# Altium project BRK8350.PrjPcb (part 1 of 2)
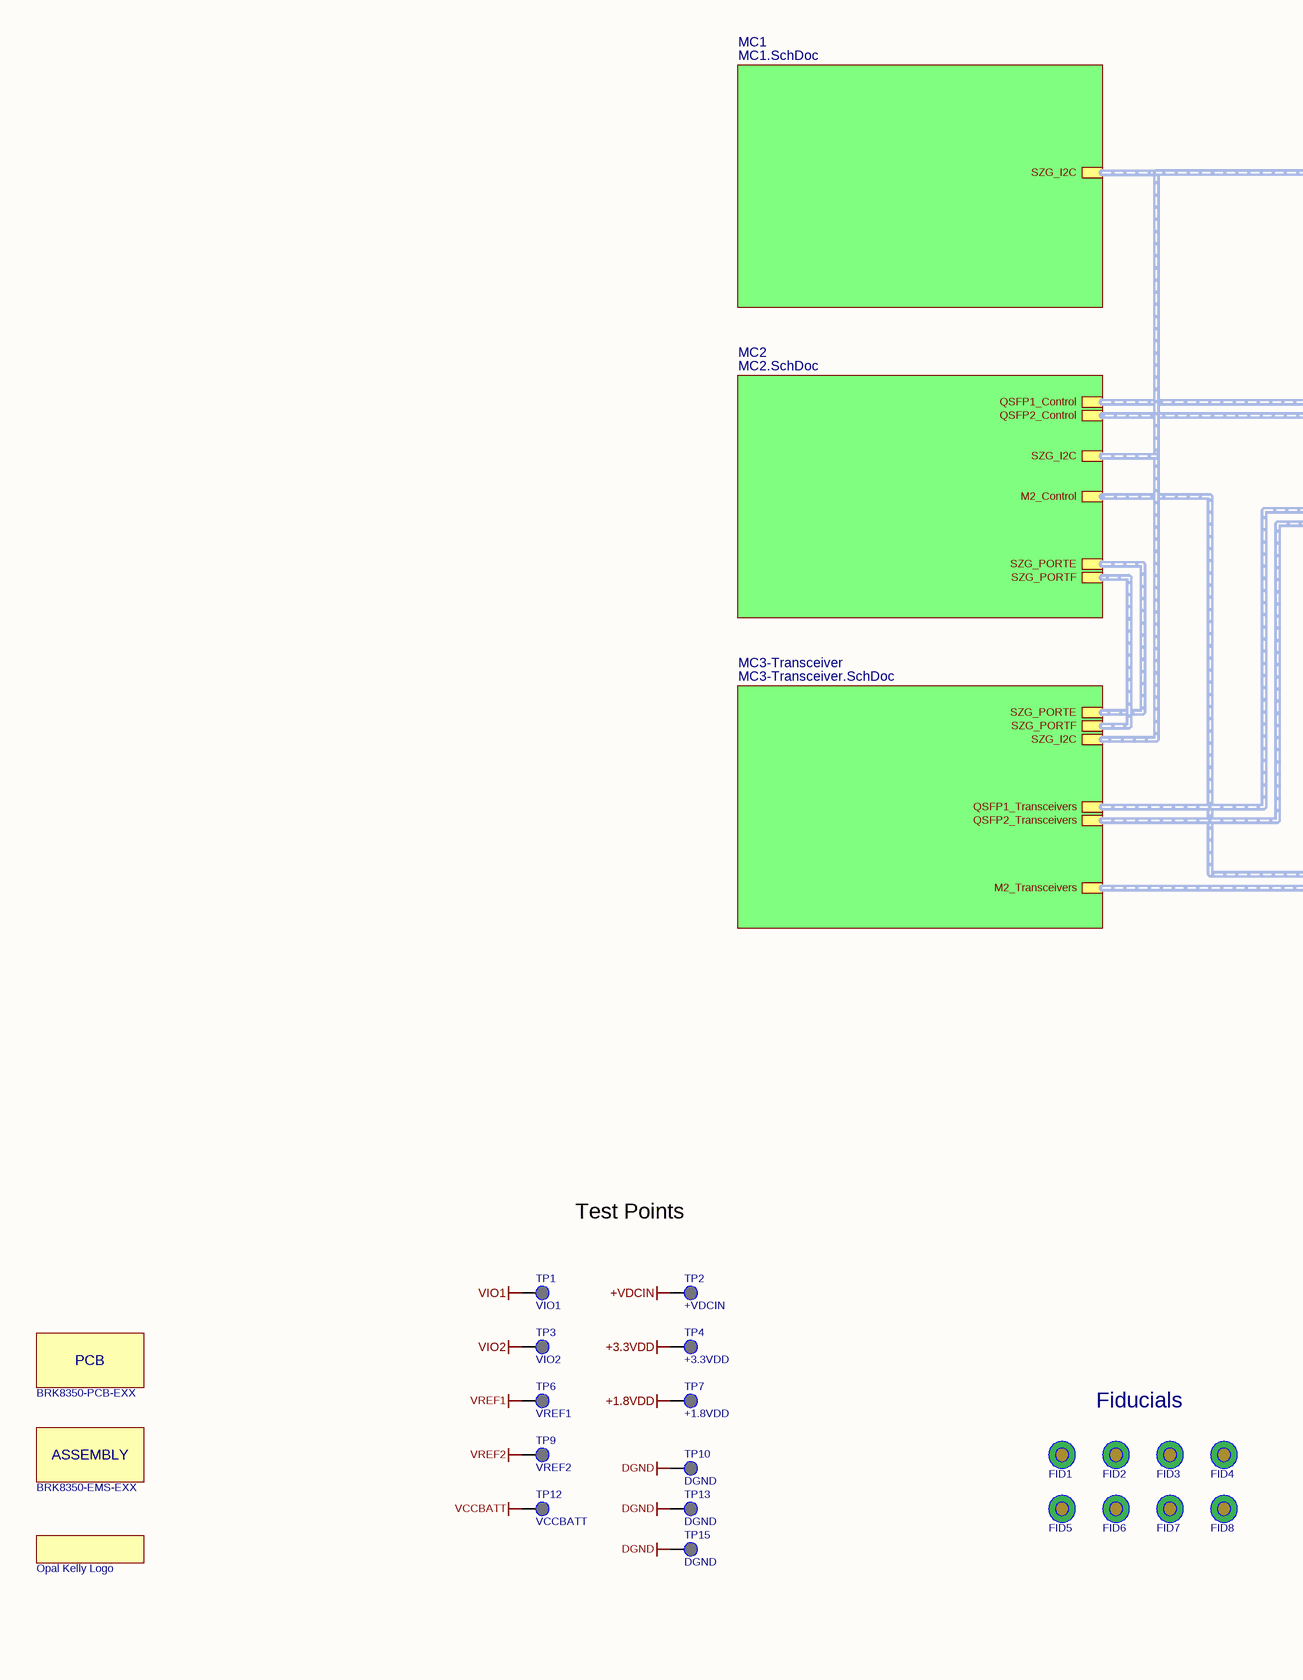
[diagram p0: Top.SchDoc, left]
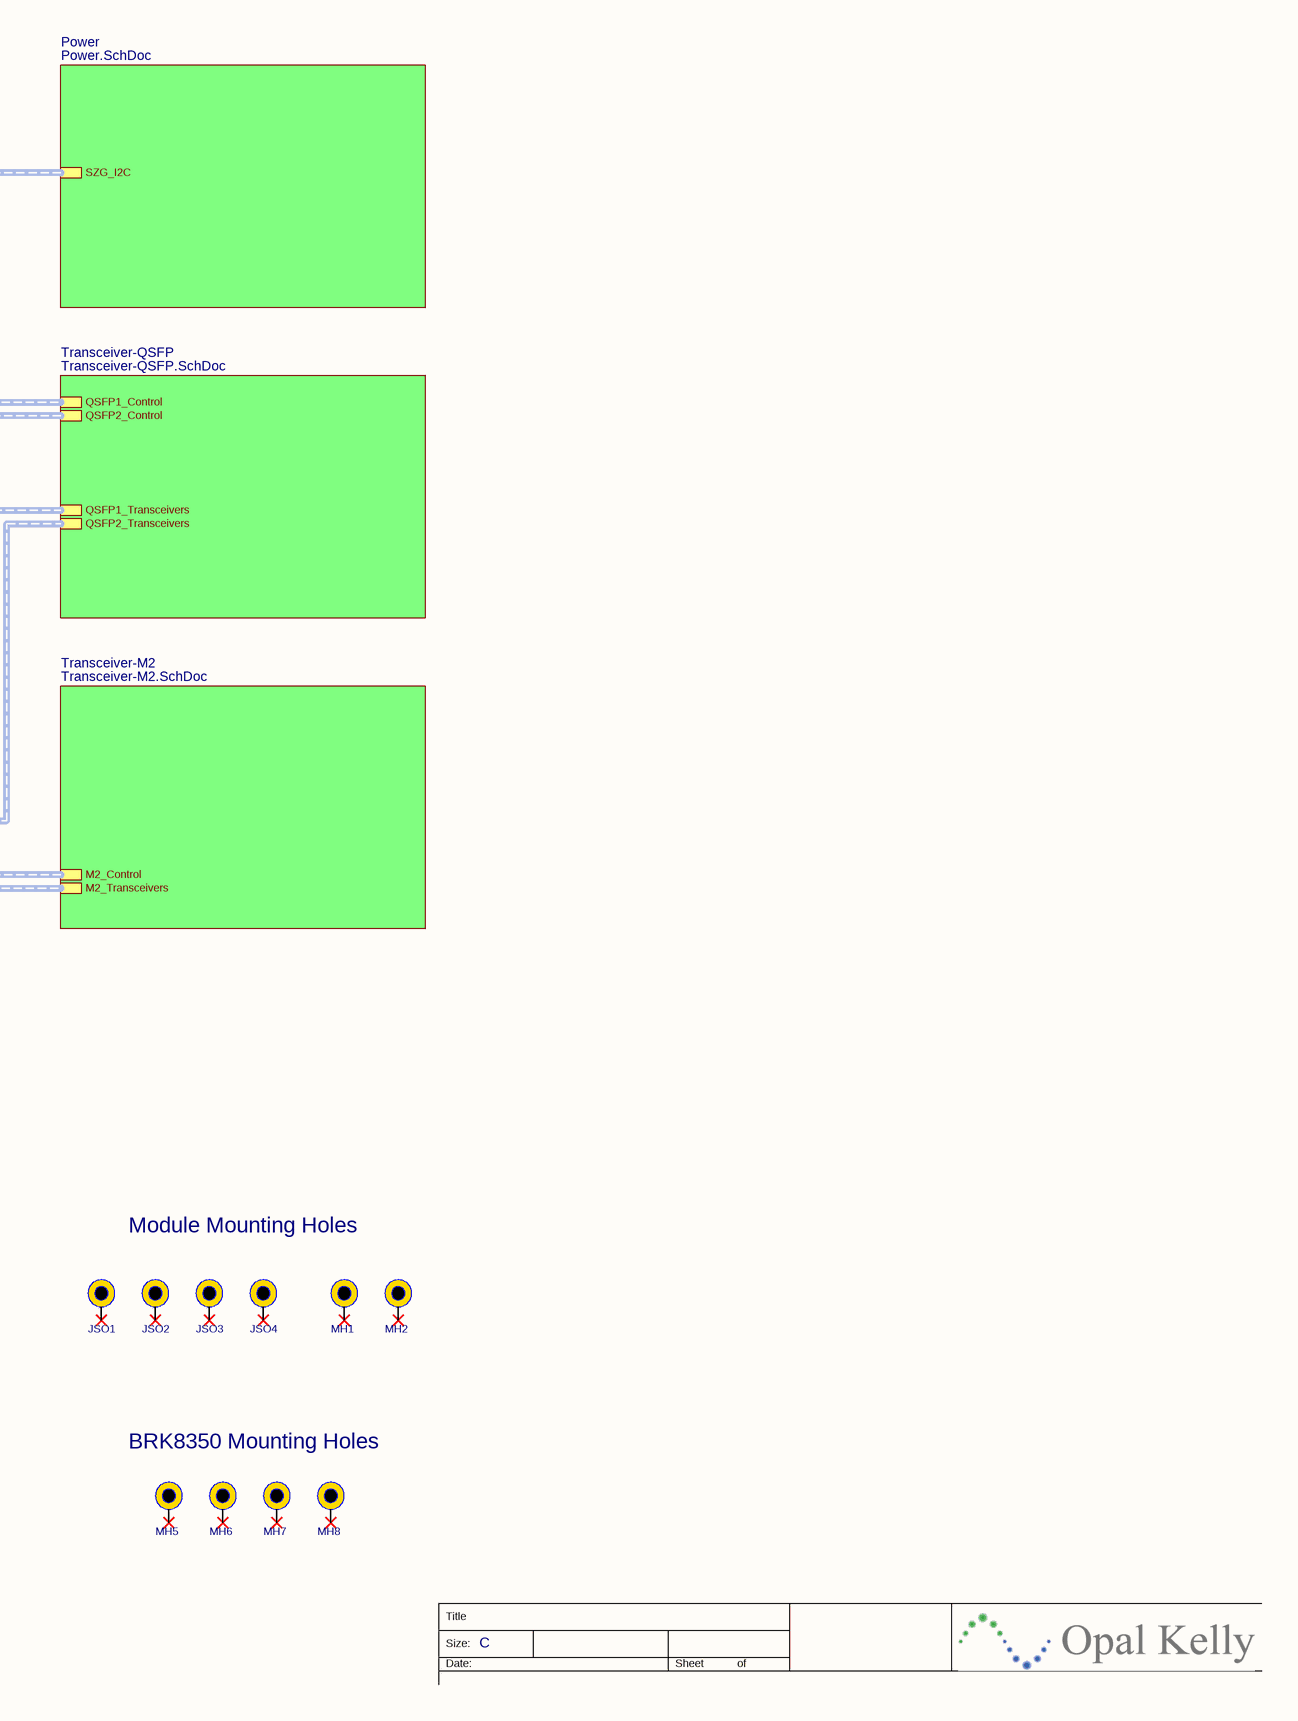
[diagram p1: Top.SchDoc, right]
BOM_Revision: 02; Part_Number: BRK8350; PCB_Revision: E; VariantBoms: Default=001770
7 sheets, 281 parts. Net scope: hierarchical (ports join the sheet entries above them; power ports are global).
Board file: BRK8350.PcbDoc
Sheets:
  Top.SchDoc
    Transceiver-QSFP = Transceiver-QSFP.SchDoc
    MC2 = MC2.SchDoc
    MC1 = MC1.SchDoc
    Power = Power.SchDoc
    Transceiver-M2 = Transceiver-M2.SchDoc
    MC3-Transceiver = MC3-Transceiver.SchDoc

## Sheet Top.SchDoc: BRK8350 - Top Level
size C; Organization: Opal Kelly; Address1: 13500 SW 72nd Ave STE 100; Address3: Portland, OR  97223; Address4: http://www.opalkelly.com; DocumentNumber: xxx; Revision: 1; SheetNumber: 1; SheetTotal: 7; PageSetup: Record=PageOptions¦CenterHorizontal=True¦CenterVertical=True¦PrintScale=0.52¦XCorrection=1.00¦YCorrection=1.00¦PrintKind=0¦BorderSize=5000000¦LeftOffset=0¦BottomOffset=0¦Orientation=2¦PaperLength=1000¦PaperWidth=1000¦Scale=100¦PaperSource=15¦PrintQuality=600¦MediaType=1¦DitherType=10¦PaperKind=Letter¦PrintScaleMode=1

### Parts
*1  Opal Kelly Logo  [okLogo-23x5]
ASSY1  BRK8350-EMS-EXX  (mechanical)
FID1  FIDUCIAL  [FID1MM/2MM-SS]  (value not drawn)
FID2  FIDUCIAL  [FID1MM/2MM-SS]  (value not drawn)
FID3  FIDUCIAL  [FID1MM/2MM-SS]  (value not drawn)
FID4  FIDUCIAL  [FID1MM/2MM-SS]  (value not drawn)
FID5  FIDUCIAL  [FID1MM/2MM-SS]  (value not drawn)
FID6  FIDUCIAL  [FID1MM/2MM-SS]  (value not drawn)
FID7  FIDUCIAL  [FID1MM/2MM-SS]  (value not drawn)
FID8  FIDUCIAL  [FID1MM/2MM-SS]  (value not drawn)
JSO1  Jack Screw Standoff  [JSO-0515-01]  (value not drawn)
JSO2  Jack Screw Standoff  [JSO-0515-01]  (value not drawn)
JSO3  Jack Screw Standoff  [JSO-0515-01]  (value not drawn)
JSO4  Jack Screw Standoff  [JSO-0515-01]  (value not drawn)
MH1  MTG  [MTG-3.2/6.5-PTH]  (value not drawn)
MH2  MTG  [MTG-3.2/6.5-PTH]  (value not drawn)
MH5  MTG  [MTG-3.2/6.5-PTH]  (value not drawn)
MH6  MTG  [MTG-3.2/6.5-PTH]  (value not drawn)
MH7  MTG  [MTG-3.2/6.5-PTH]  (value not drawn)
MH8  MTG  [MTG-3.2/6.5-PTH]  (value not drawn)
PCB1  BRK8350-PCB-EXX  (mechanical)
TP1  VIO1  [TP-PTH-65/100]
TP2  +VDCIN  [TP-PTH-65/100]
TP3  VIO2  [TP-PTH-65/100]
TP4  +3.3VDD  [TP-PTH-65/100]
TP6  VREF1  [TP-PTH-65/100]
TP7  +1.8VDD  [TP-PTH-65/100]
TP9  VREF2  [TP-PTH-65/100]
TP10  DGND  [TP-PTH-65/100]
TP12  VCCBATT  [TP-PTH-65/100]
TP13  DGND  [TP-PTH-65/100]
TP15  DGND  [TP-PTH-65/100]

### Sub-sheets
MC1 = MC1.SchDoc: SZG_I2C (harness I2C)
MC2 = MC2.SchDoc: SZG_PORTE (harness SYZYGY_TXR4), SZG_PORTF (harness SYZYGY_TXR4), QSFP1_Control (harness QSFP_Control), M2_Control (harness M2_Control), QSFP2_Control (harness QSFP_Control), SZG_I2C (harness I2C)
MC3-Transceiver = MC3-Transceiver.SchDoc: SZG_PORTE (harness SYZYGY_TXR4), SZG_PORTF (harness SYZYGY_TXR4), SZG_I2C (harness I2C), M2_Transceivers (harness M2_Transceivers), QSFP1_Transceivers (harness QSFP_Transceivers), QSFP2_Transceivers (harness QSFP_Transceivers)
Power = Power.SchDoc: SZG_I2C (harness I2C)
Transceiver-M2 = Transceiver-M2.SchDoc: M2_Transceivers (harness M2_Transceivers), M2_Control (harness M2_Control)
Transceiver-QSFP = Transceiver-QSFP.SchDoc: QSFP1_Control (harness QSFP_Control), QSFP2_Control (harness QSFP_Control), QSFP1_Transceivers (harness QSFP_Transceivers), QSFP2_Transceivers (harness QSFP_Transceivers)

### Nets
+1.8VDD: TP7.1(PIN)
+3.3VDD: TP4.1(PIN)
+VDCIN: TP2.1(PIN)
DGND: TP10.1(PIN) TP13.1(PIN) TP15.1(PIN)
VCCBATT: TP12.1(PIN)
VIO1: TP1.1(PIN)
VIO2: TP3.1(PIN)
VREF1: TP6.1(PIN)
VREF2: TP9.1(PIN)

Not connected (* = marked no-connect by the designer): JSO1 1*; JSO2 1*; JSO3 1*; JSO4 1*; MH1 1*; MH2 1*; MH5 1*; MH6 1*; MH7 1*; MH8 1*

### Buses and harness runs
harness sheet MC1/SZG_I2C = sheet MC2/SZG_I2C = sheet MC3-Transceiver/SZG_I2C = sheet Power/SZG_I2C
harness sheet MC2/M2_Control = sheet Transceiver-M2/M2_Control
harness sheet MC2/QSFP1_Control = sheet Transceiver-QSFP/QSFP1_Control
harness sheet MC2/QSFP2_Control = sheet Transceiver-QSFP/QSFP2_Control
harness sheet MC2/SZG_PORTE = sheet MC3-Transceiver/SZG_PORTE
harness sheet MC2/SZG_PORTF = sheet MC3-Transceiver/SZG_PORTF
harness sheet MC3-Transceiver/M2_Transceivers = sheet Transceiver-M2/M2_Transceivers
harness sheet MC3-Transceiver/QSFP1_Transceivers = sheet Transceiver-QSFP/QSFP1_Transceivers
harness sheet MC3-Transceiver/QSFP2_Transceivers = sheet Transceiver-QSFP/QSFP2_Transceivers

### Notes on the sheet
- Test Points
- Module Mounting Holes
- Fiducials
- BRK8350 Mounting Holes
- Title
- Size:
- Date:
- C
- Sheet
- of

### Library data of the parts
*1 = OKLOGO: partnumber: ALIGNI_IGNORE
ASSY1 = 001928: Assembly Service; Partnumber: 001928; manufacturer: PCB Assembly Cost; description: BRK8350 PCB assembly
FID1-FID8 = FIDUCIAL: PCB fiducial; partnumber: ALIGNI_IGNORE
JSO1-JSO4 = 001879: Mounting hole; Partnumber: 001879; manufacturer: Samtec
MH1 MH2 MH5-MH8 = MTG: Mounting hole; partnumber: ALIGNI_IGNORE
PCB1 = 001929: PCB; Partnumber: 001929; manufacturer: Generic PCB Manufacturer; description: PCB for BRK8350
TP1-TP4 TP6 TP7 TP9 TP10 TP12 TP13 TP15 = TP-PTH-65/100: Test point, plated through-hole, 65/100mil; partnumber: ALIGNI_IGNORE

## Sheet Transceiver-QSFP.SchDoc: BRK8350 - QSFP
size C; Author: Casey Smith; Organization: Opal Kelly; Address1: 13500 SW 72nd Ave STE 100; Address2: Portland, OR 97223; Address3: 217.391.3724; Address4: http://www.opalkelly.com; DocumentNumber: xxx; Revision: 1; SheetNumber: 5; SheetTotal: 7
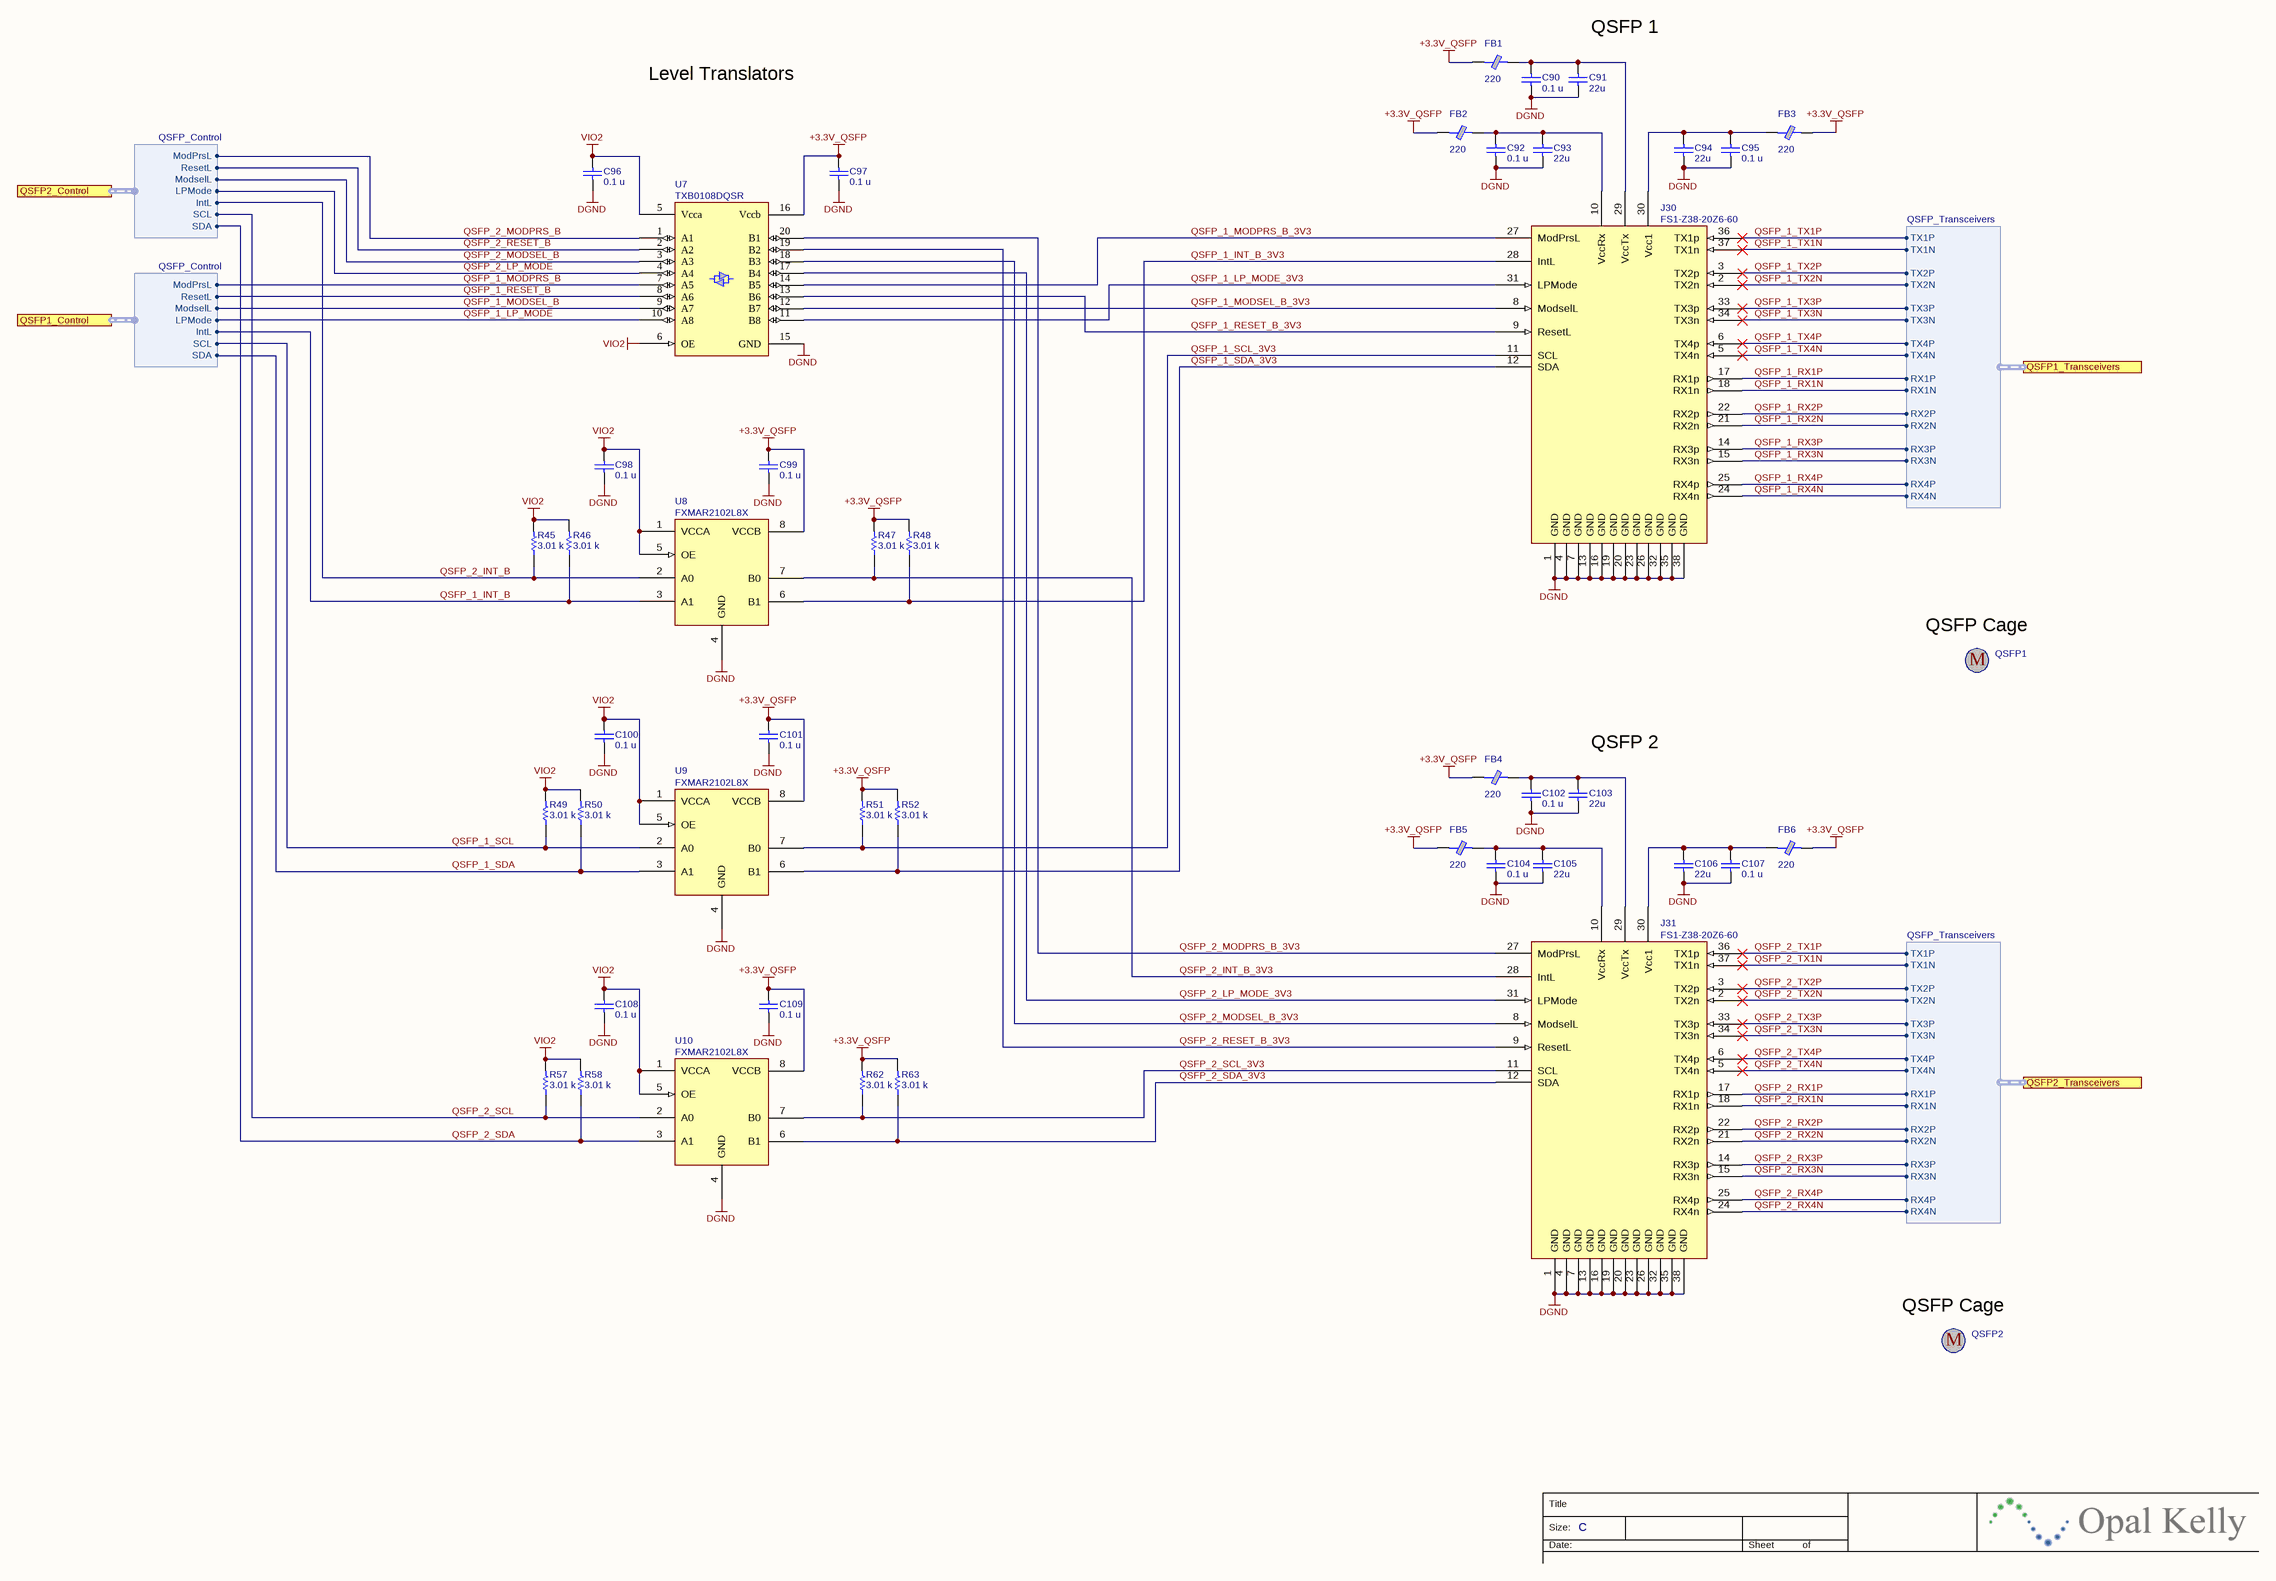
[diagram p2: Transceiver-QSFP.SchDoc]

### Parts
C90  value 0.1 u  [CAPC1005X06A]  (hidden comment: SM-0402, 10%, 10v)
C91  value 22u  [CAPC3216N]  (hidden comment: SM-1206, 10%, 10v, X7R)
C92  value 0.1 u  [CAPC1005X06A]  (hidden comment: SM-0402, 10%, 10v)
C93  value 22u  [CAPC3216N]  (hidden comment: SM-1206, 10%, 10v, X7R)
C94  value 22u  [CAPC3216N]  (hidden comment: SM-1206, 10%, 10v, X7R)
C95  value 0.1 u  [CAPC1005X06A]  (hidden comment: SM-0402, 10%, 10v)
C96  value 0.1 u  [CAPC1005X06A]  (hidden comment: SM-0402, 10%, 10v)
C97  value 0.1 u  [CAPC1005X06A]  (hidden comment: SM-0402, 10%, 10v)
C98  value 0.1 u  [CAPC1005X06A]  (hidden comment: SM-0402, 10%, 10v)
C99  value 0.1 u  [CAPC1005X06A]  (hidden comment: SM-0402, 10%, 10v)
C100  value 0.1 u  [CAPC1005X06A]  (hidden comment: SM-0402, 10%, 10v)
C101  value 0.1 u  [CAPC1005X06A]  (hidden comment: SM-0402, 10%, 10v)
C102  value 0.1 u  [CAPC1005X06A]  (hidden comment: SM-0402, 10%, 10v)
C103  value 22u  [CAPC3216N]  (hidden comment: SM-1206, 10%, 10v, X7R)
C104  value 0.1 u  [CAPC1005X06A]  (hidden comment: SM-0402, 10%, 10v)
C105  value 22u  [CAPC3216N]  (hidden comment: SM-1206, 10%, 10v, X7R)
C106  value 22u  [CAPC3216N]  (hidden comment: SM-1206, 10%, 10v, X7R)
C107  value 0.1 u  [CAPC1005X06A]  (hidden comment: SM-0402, 10%, 10v)
C108  value 0.1 u  [CAPC1005X06A]  (hidden comment: SM-0402, 10%, 10v)
C109  value 0.1 u  [CAPC1005X06A]  (hidden comment: SM-0402, 10%, 10v)
FB1  value 220  [RESC2012N]  (hidden comment: 220 OHM 2000MA 0805)
FB2  value 220  [RESC2012N]  (hidden comment: 220 OHM 2000MA 0805)
FB3  value 220  [RESC2012N]  (hidden comment: 220 OHM 2000MA 0805)
FB4  value 220  [RESC2012N]  (hidden comment: 220 OHM 2000MA 0805)
FB5  value 220  [RESC2012N]  (hidden comment: 220 OHM 2000MA 0805)
FB6  value 220  [RESC2012N]  (hidden comment: 220 OHM 2000MA 0805)
J30  FS1-Z38-20Z6-60  [QSFP28_RECEPTACLE_SFF-8679]
J31  FS1-Z38-20Z6-60  [QSFP28_RECEPTACLE_SFF-8679]
QSFP1  Pressfit  [QSFP28_SINGLE_CAGE]  (value not drawn)
QSFP2  Pressfit  [QSFP28_SINGLE_CAGE]  (value not drawn)
R45  value 3.01 k  [RESC1005X06A]  (hidden comment: SM-0402, 1%, 1/16W)
R46  value 3.01 k  [RESC1005X06A]  (hidden comment: SM-0402, 1%, 1/16W)
R47  value 3.01 k  [RESC1005X06A]  (hidden comment: SM-0402, 1%, 1/16W)
R48  value 3.01 k  [RESC1005X06A]  (hidden comment: SM-0402, 1%, 1/16W)
R49  value 3.01 k  [RESC1005X06A]  (hidden comment: SM-0402, 1%, 1/16W)
R50  value 3.01 k  [RESC1005X06A]  (hidden comment: SM-0402, 1%, 1/16W)
R51  value 3.01 k  [RESC1005X06A]  (hidden comment: SM-0402, 1%, 1/16W)
R52  value 3.01 k  [RESC1005X06A]  (hidden comment: SM-0402, 1%, 1/16W)
R57  value 3.01 k  [RESC1005X06A]  (hidden comment: SM-0402, 1%, 1/16W)
R58  value 3.01 k  [RESC1005X06A]  (hidden comment: SM-0402, 1%, 1/16W)
R62  value 3.01 k  [RESC1005X06A]  (hidden comment: SM-0402, 1%, 1/16W)
R63  value 3.01 k  [RESC1005X06A]  (hidden comment: SM-0402, 1%, 1/16W)
U7  TXB0108DQSR  [TXB0108DQSR]
U8  FXMAR2102L8X  [FXMAR2102L8X]
U9  FXMAR2102L8X  [FXMAR2102L8X]
U10  FXMAR2102L8X  [FXMAR2102L8X]

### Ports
QSFP1_Control (harness QSFP_Control), QSFP1_Transceivers (harness QSFP_Transceivers), QSFP2_Control (harness QSFP_Control), QSFP2_Transceivers (harness QSFP_Transceivers)

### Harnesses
QSFP_Transceivers: TX1P, TX1N, TX2P, TX2N, TX3P, TX3N, TX4P, TX4N, RX1P, RX1N, RX2P, RX2N, RX3P, RX3N, RX4P, RX4N
QSFP_Control: ModPrsL, IntL, LPMode, ModselL, ResetL, SCL, SDA

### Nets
+3.3V_QSFP: C97.2 C99.2 C101.2 C109.2 FB1.1 FB2.1 FB3.2 FB4.1 FB5.1 FB6.2 R47.2 R48.2 R51.2 R52.2 R62.2 R63.2 U7.16(Vccb) U8.8(VCCB) U9.8(VCCB) U10.8(VCCB)
DGND: C90.1 C91.1 C92.1 C93.1 C94.1 C95.1 C96.1 C97.1 C98.1 C99.1 C100.1 C101.1 C102.1 C103.1 C104.1 C105.1 C106.1 C107.1 C108.1 C109.1 J30.1(GND) J30.4(GND) J30.7(GND) J30.13(GND) J30.16(GND) J30.19(GND) J30.20(GND) J30.23(GND) J30.26(GND) J30.32(GND) J30.35(GND) J30.38(GND) J31.1(GND) J31.4(GND) J31.7(GND) J31.13(GND) J31.16(GND) J31.19(GND) J31.20(GND) J31.23(GND) J31.26(GND) J31.32(GND) J31.35(GND) J31.38(GND) U7.15(GND) U8.4(GND) U9.4(GND) U10.4(GND)
VIO2: C96.2 C98.2 C100.2 C108.2 R45.2 R46.2 R49.2 R50.2 R57.2 R58.2 U7.5(Vcca) U7.6(OE) U8.1(VCCA) U8.5(OE) U9.1(VCCA) U9.5(OE) U10.1(VCCA) U10.5(OE)
QSFP_1_INT_B: R46.1 U8.3(A1) ; port QSFP1_Control.IntL
QSFP_1_INT_B_3V3: J30.28(IntL) R48.1 U8.6(B1)
QSFP_1_LP_MODE: U7.10(A8) ; port QSFP1_Control.LPMode
QSFP_1_LP_MODE_3V3: J30.31(LPMode) U7.11(B8)
QSFP_1_MODPRS_B: U7.7(A5) ; port QSFP1_Control.ModPrsL
QSFP_1_MODPRS_B_3V3: J30.27(ModPrsL) U7.14(B5)
QSFP_1_MODSEL_B: U7.9(A7) ; port QSFP1_Control.ModselL
QSFP_1_MODSEL_B_3V3: J30.8(ModselL) U7.12(B7)
QSFP_1_RESET_B: U7.8(A6) ; port QSFP1_Control.ResetL
QSFP_1_RESET_B_3V3: J30.9(ResetL) U7.13(B6)
QSFP_1_RX1N: J30.18(RX1n) ; port QSFP1_Transceivers.RX1N
QSFP_1_RX1P: J30.17(RX1p) ; port QSFP1_Transceivers.RX1P
QSFP_1_RX2N: J30.21(RX2n) ; port QSFP1_Transceivers.RX2N
QSFP_1_RX2P: J30.22(RX2p) ; port QSFP1_Transceivers.RX2P
QSFP_1_RX3N: J30.15(RX3n) ; port QSFP1_Transceivers.RX3N
QSFP_1_RX3P: J30.14(RX3p) ; port QSFP1_Transceivers.RX3P
QSFP_1_RX4N: J30.24(RX4n) ; port QSFP1_Transceivers.RX4N
QSFP_1_RX4P: J30.25(RX4p) ; port QSFP1_Transceivers.RX4P
QSFP_1_SCL: R49.1 U9.2(A0) ; port QSFP1_Control.SCL
QSFP_1_SCL_3V3: J30.11(SCL) R51.1 U9.7(B0)
QSFP_1_SDA: R50.1 U9.3(A1) ; port QSFP1_Control.SDA
QSFP_1_SDA_3V3: J30.12(SDA) R52.1 U9.6(B1)
QSFP_1_TX1N: J30.37(TX1n) ; port QSFP1_Transceivers.TX1N
QSFP_1_TX1P: J30.36(TX1p) ; port QSFP1_Transceivers.TX1P
QSFP_1_TX2N: J30.2(TX2n) ; port QSFP1_Transceivers.TX2N
QSFP_1_TX2P: J30.3(TX2p) ; port QSFP1_Transceivers.TX2P
QSFP_1_TX3N: J30.34(TX3n) ; port QSFP1_Transceivers.TX3N
QSFP_1_TX3P: J30.33(TX3p) ; port QSFP1_Transceivers.TX3P
QSFP_1_TX4N: J30.5(TX4n) ; port QSFP1_Transceivers.TX4N
QSFP_1_TX4P: J30.6(TX4p) ; port QSFP1_Transceivers.TX4P
QSFP_2_INT_B: R45.1 U8.2(A0) ; port QSFP2_Control.IntL
QSFP_2_INT_B_3V3: J31.28(IntL) R47.1 U8.7(B0)
QSFP_2_LP_MODE: U7.4(A4) ; port QSFP2_Control.LPMode
QSFP_2_LP_MODE_3V3: J31.31(LPMode) U7.17(B4)
QSFP_2_MODPRS_B: U7.1(A1) ; port QSFP2_Control.ModPrsL
QSFP_2_MODPRS_B_3V3: J31.27(ModPrsL) U7.20(B1)
QSFP_2_MODSEL_B: U7.3(A3) ; port QSFP2_Control.ModselL
QSFP_2_MODSEL_B_3V3: J31.8(ModselL) U7.18(B3)
QSFP_2_RESET_B: U7.2(A2) ; port QSFP2_Control.ResetL
QSFP_2_RESET_B_3V3: J31.9(ResetL) U7.19(B2)
QSFP_2_RX1N: J31.18(RX1n) ; port QSFP2_Transceivers.RX1N
QSFP_2_RX1P: J31.17(RX1p) ; port QSFP2_Transceivers.RX1P
QSFP_2_RX2N: J31.21(RX2n) ; port QSFP2_Transceivers.RX2N
QSFP_2_RX2P: J31.22(RX2p) ; port QSFP2_Transceivers.RX2P
QSFP_2_RX3N: J31.15(RX3n) ; port QSFP2_Transceivers.RX3N
QSFP_2_RX3P: J31.14(RX3p) ; port QSFP2_Transceivers.RX3P
QSFP_2_RX4N: J31.24(RX4n) ; port QSFP2_Transceivers.RX4N
QSFP_2_RX4P: J31.25(RX4p) ; port QSFP2_Transceivers.RX4P
QSFP_2_SCL: R57.1 U10.2(A0) ; port QSFP2_Control.SCL
QSFP_2_SCL_3V3: J31.11(SCL) R62.1 U10.7(B0)
QSFP_2_SDA: R58.1 U10.3(A1) ; port QSFP2_Control.SDA
QSFP_2_SDA_3V3: J31.12(SDA) R63.1 U10.6(B1)
QSFP_2_TX1N: J31.37(TX1n) ; port QSFP2_Transceivers.TX1N
QSFP_2_TX1P: J31.36(TX1p) ; port QSFP2_Transceivers.TX1P
QSFP_2_TX2N: J31.2(TX2n) ; port QSFP2_Transceivers.TX2N
QSFP_2_TX2P: J31.3(TX2p) ; port QSFP2_Transceivers.TX2P
QSFP_2_TX3N: J31.34(TX3n) ; port QSFP2_Transceivers.TX3N
QSFP_2_TX3P: J31.33(TX3p) ; port QSFP2_Transceivers.TX3P
QSFP_2_TX4N: J31.5(TX4n) ; port QSFP2_Transceivers.TX4N
QSFP_2_TX4P: J31.6(TX4p) ; port QSFP2_Transceivers.TX4P
NetC90_2: C90.2 C91.2 FB1.2 J30.29(VccTx)
NetC92_2: C92.2 C93.2 FB2.2 J30.10(VccRx)
NetC94_2: C94.2 C95.2 FB3.1 J30.30(Vcc1)
NetC102_2: C102.2 C103.2 FB4.2 J31.29(VccTx)
NetC104_2: C104.2 C105.2 FB5.2 J31.10(VccRx)
NetC106_2: C106.2 C107.2 FB6.1 J31.30(Vcc1)

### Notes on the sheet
- (near C91) QSFP 1
- Level Translators
- (near QSFP1) QSFP Cage
- (near C103) QSFP 2
- (near QSFP2) QSFP Cage
- Title
- Size:
- Date:
- C
- Sheet
- of

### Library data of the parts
C90 C92 C95-C102 C104 C107-C109 = 000070: Partnumber: 000070; manufacturer: Kemet; manufacturer_pn: C0402C104K8PACTU; ValueFloat: 1E-7; id: 750; inventory_price: 0.0023; reorder_quantity: 70000; x_tolerance: 10
C91 C93 C94 C103 C105 C106 = 001284: Partnumber: 001284; manufacturer: Taiyo Yuden; manufacturer_pn: LMK316AB7226KL-TR; ValueFloat: 2.2E-5; id: 60625; inventory_price: 0.14; reorder_quantity: 4000; x_tolerance: 10
FB1-FB6 = 000783: Partnumber: 000783; manufacturer: Murata; manufacturer_pn: BLM21PG221SN1D; id: 12845; inventory_price: 0.02; reorder_quantity: 200
J30 J31 = 001782: Partnumber: 001782; manufacturer: Amphenol; id: 254667; inventory_price: 4
QSFP1 QSFP2 = 001781: Partnumber: 001781; manufacturer: Amphenol; manufacturer_pn: U95-T111-1001; id: 254666; inventory_price: 3.5
R45-R52 R57 R58 R62 R63 = 001126: Partnumber: 001126; manufacturer: Vishay; manufacturer_pn: CRCW04023K01FKED; ValueFloat: 3010; id: 35682; inventory_price: 0.015; x_tolerance: 1
U7 = 001324: Partnumber: 001324; manufacturer: Texas Instruments; id: 94563; inventory_price: 1.67
U8-U10 = 001559: Partnumber: 001559; manufacturer: ON Semiconductor; id: 168047; inventory_price: 0.3

## Sheet MC2.SchDoc: BRK8350 - Mezzanine Connector MC2
size C; Author: Casey Smith; Organization: Opal Kelly; Address1: 13500 SW 72nd Ave STE 100; Address2: Portland, OR 97223; Address3: 217.391.3724; Address4: http://www.opalkelly.com; DocumentNumber: xxx; Revision: 1; SheetNumber: 3; SheetTotal: 7
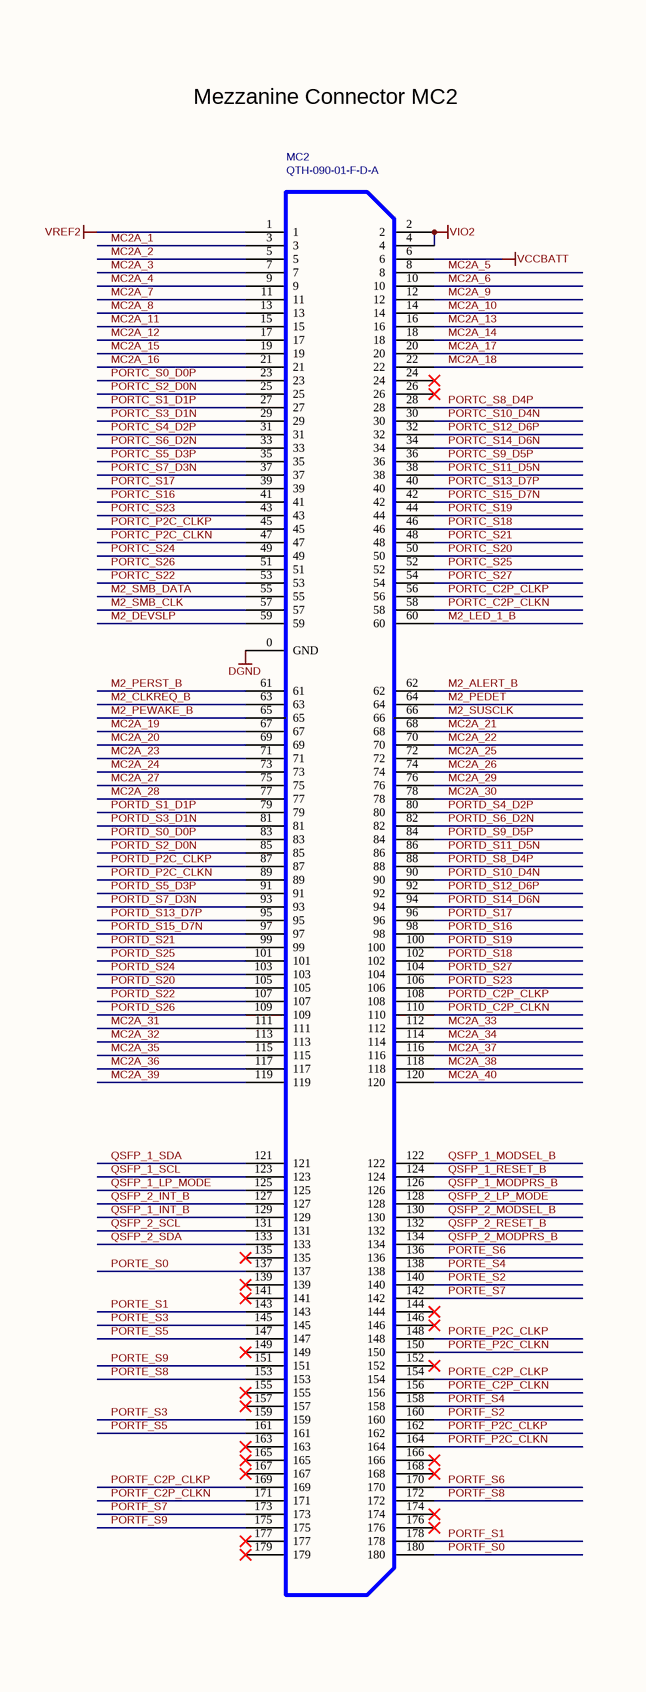
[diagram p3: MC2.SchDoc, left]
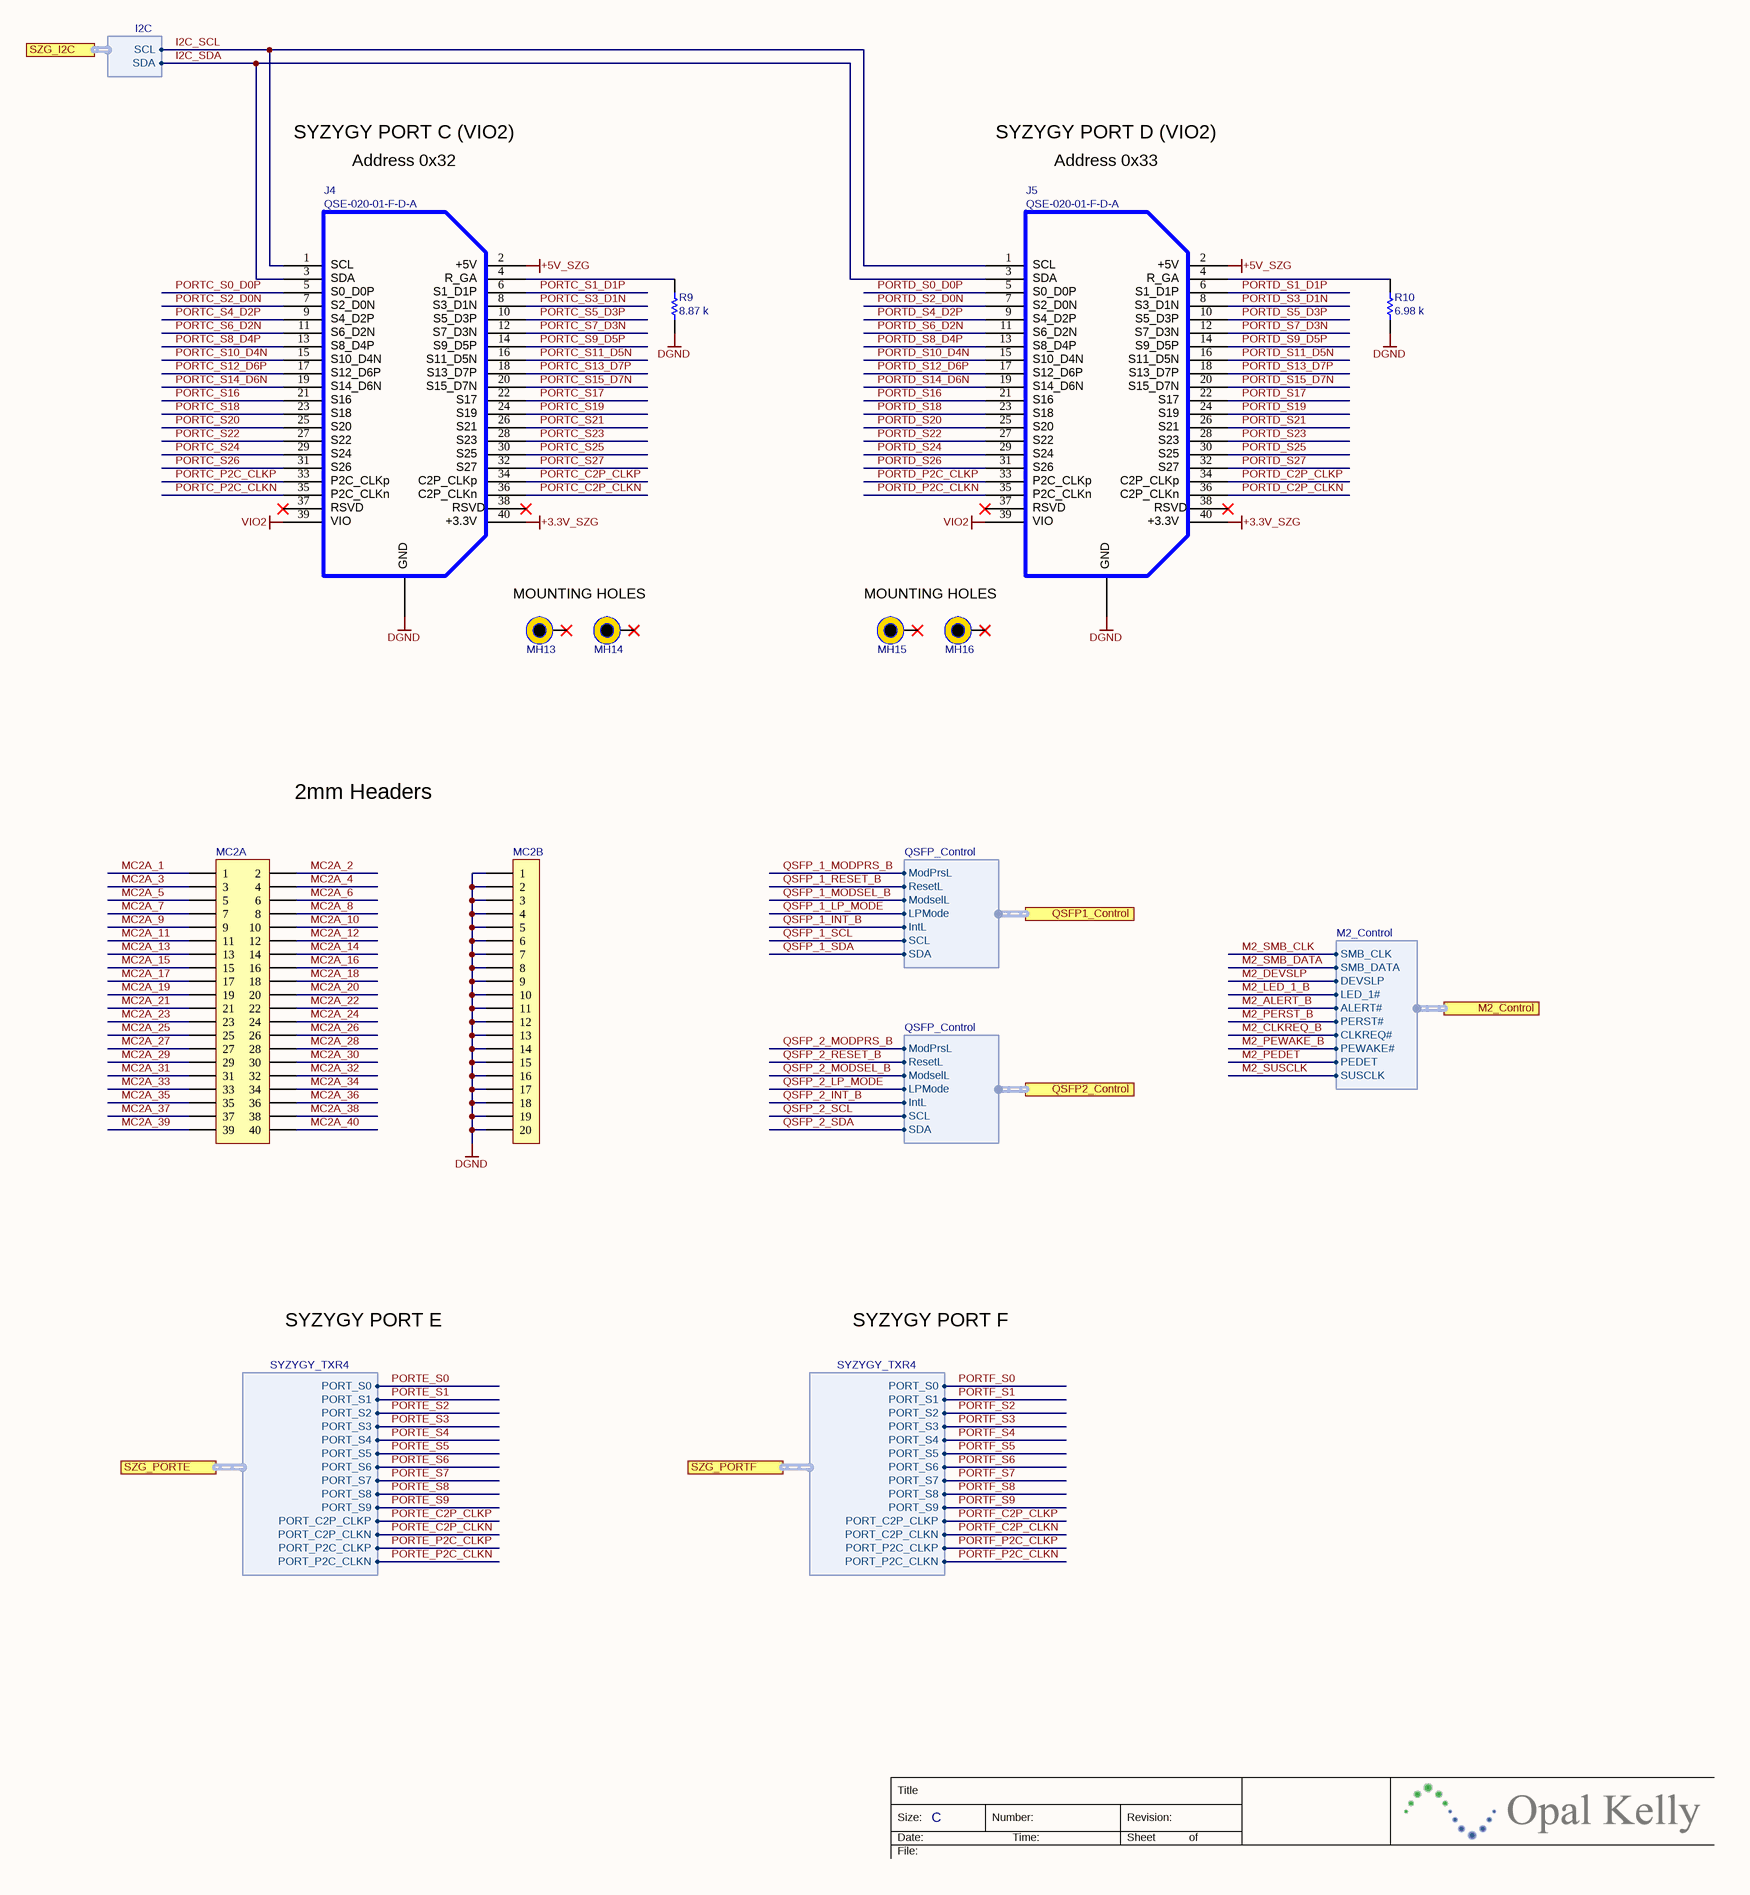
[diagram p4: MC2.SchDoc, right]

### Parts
J4  QSE-020-01-F-D-A  [QSE-020-01-X-D-A-L]
J5  QSE-020-01-F-D-A  [QSE-020-01-X-D-A-L]
MC2  QTH-090-01-F-D-A  [QTH-090-01-X-D]
MC2A  0877584016  [HDR2X20-2MM]  (value not drawn)
MC2B  Header, 20-Pin, Single Row  [HDR1X20-2MM]  (value not drawn)
MH13  MTG  [MTG-3.2/6.5-PTH]  (value not drawn)
MH14  MTG  [MTG-3.2/6.5-PTH]  (value not drawn)
MH15  MTG  [MTG-3.2/6.5-PTH]  (value not drawn)
MH16  MTG  [MTG-3.2/6.5-PTH]  (value not drawn)
R9  value 8.87 k  [RESC1005X06A]  (hidden comment: RC0402FR-078K87L)
R10  value 6.98 k  [RESC1005X06A]  (hidden comment: RC0402FR-076K98L)

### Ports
M2_Control (harness M2_Control), QSFP1_Control (harness QSFP_Control), QSFP2_Control (harness QSFP_Control), SZG_I2C (harness I2C), SZG_PORTE (harness SYZYGY_TXR4), SZG_PORTF (harness SYZYGY_TXR4)

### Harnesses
I2C: SCL, SDA
SYZYGY_TXR4: PORT_S0, PORT_S1, PORT_S2, PORT_S3, PORT_S4, PORT_S5, PORT_S6, PORT_S7, PORT_S8, PORT_S9, PORT_C2P_CLKP, PORT_C2P_CLKN, PORT_P2C_CLKP, PORT_P2C_CLKN
M2_Control: DEVSLP, SMB_CLK, SMB_DATA, ALERT#, PERST#, CLKREQ#, PEWAKE#, LED_1#, SUSCLK, PEDET
QSFP_Control: ModPrsL, IntL, LPMode, ModselL, ResetL, SCL, SDA

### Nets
+3.3V_SZG: J4.40 J5.40
+5V_SZG: J4.2 J5.2
DGND: J4.0 J5.0 MC2.0(GND) MC2B.1 MC2B.2 MC2B.3 MC2B.4 MC2B.5 MC2B.6 MC2B.7 MC2B.8 MC2B.9 MC2B.10 MC2B.11 MC2B.12 MC2B.13 MC2B.14 MC2B.15 MC2B.16 MC2B.17 MC2B.18 MC2B.19 MC2B.20 R9.1 R10.1
VCCBATT: MC2.6
VIO2: J4.39 J5.39 MC2.2 MC2.4
VREF2: MC2.1
I2C_SCL: J4.1 J5.1 ; port SZG_I2C.SCL
I2C_SDA: J4.3 J5.3 ; port SZG_I2C.SDA
M2_ALERT_B: MC2.62 ; port M2_Control.ALERT#
M2_CLKREQ_B: MC2.63 ; port M2_Control.CLKREQ#
M2_DEVSLP: MC2.59 ; port M2_Control.DEVSLP
M2_LED_1_B: MC2.60 ; port M2_Control.LED_1#
M2_PEDET: MC2.64 ; port M2_Control.PEDET
M2_PERST_B: MC2.61 ; port M2_Control.PERST#
M2_PEWAKE_B: MC2.65 ; port M2_Control.PEWAKE#
M2_SMB_CLK: MC2.57 ; port M2_Control.SMB_CLK
M2_SMB_DATA: MC2.55 ; port M2_Control.SMB_DATA
M2_SUSCLK: MC2.66 ; port M2_Control.SUSCLK
MC2A_1: MC2.3 MC2A.1
MC2A_2: MC2.5 MC2A.2
MC2A_3: MC2.7 MC2A.3
MC2A_4: MC2.9 MC2A.4
MC2A_5: MC2.8 MC2A.5
MC2A_6: MC2.10 MC2A.6
MC2A_7: MC2.11 MC2A.7
MC2A_8: MC2.13 MC2A.8
MC2A_9: MC2.12 MC2A.9
MC2A_10: MC2.14 MC2A.10
MC2A_11: MC2.15 MC2A.11
MC2A_12: MC2.17 MC2A.12
MC2A_13: MC2.16 MC2A.13
MC2A_14: MC2.18 MC2A.14
MC2A_15: MC2.19 MC2A.15
MC2A_16: MC2.21 MC2A.16
MC2A_17: MC2.20 MC2A.17
MC2A_18: MC2.22 MC2A.18
MC2A_19: MC2.67 MC2A.19
MC2A_20: MC2.69 MC2A.20
MC2A_21: MC2.68 MC2A.21
MC2A_22: MC2.70 MC2A.22
MC2A_23: MC2.71 MC2A.23
MC2A_24: MC2.73 MC2A.24
MC2A_25: MC2.72 MC2A.25
MC2A_26: MC2.74 MC2A.26
MC2A_27: MC2.75 MC2A.27
MC2A_28: MC2.77 MC2A.28
MC2A_29: MC2.76 MC2A.29
MC2A_30: MC2.78 MC2A.30
MC2A_31: MC2.111 MC2A.31
MC2A_32: MC2.113 MC2A.32
MC2A_33: MC2.112 MC2A.33
MC2A_34: MC2.114 MC2A.34
MC2A_35: MC2.115 MC2A.35
MC2A_36: MC2.117 MC2A.36
MC2A_37: MC2.116 MC2A.37
MC2A_38: MC2.118 MC2A.38
MC2A_39: MC2.119 MC2A.39
MC2A_40: MC2.120 MC2A.40
PORTC_C2P_CLKN: J4.36 MC2.58
PORTC_C2P_CLKP: J4.34 MC2.56
PORTC_P2C_CLKN: J4.35 MC2.47
PORTC_P2C_CLKP: J4.33 MC2.45
PORTC_S0_D0P: J4.5 MC2.23
PORTC_S1_D1P: J4.6 MC2.27
PORTC_S2_D0N: J4.7 MC2.25
PORTC_S3_D1N: J4.8 MC2.29
PORTC_S4_D2P: J4.9 MC2.31
PORTC_S5_D3P: J4.10 MC2.35
PORTC_S6_D2N: J4.11 MC2.33
PORTC_S7_D3N: J4.12 MC2.37
PORTC_S8_D4P: J4.13 MC2.28
PORTC_S9_D5P: J4.14 MC2.36
PORTC_S10_D4N: J4.15 MC2.30
PORTC_S11_D5N: J4.16 MC2.38
PORTC_S12_D6P: J4.17 MC2.32
PORTC_S13_D7P: J4.18 MC2.40
PORTC_S14_D6N: J4.19 MC2.34
PORTC_S15_D7N: J4.20 MC2.42
PORTC_S16: J4.21 MC2.41
PORTC_S17: J4.22 MC2.39
PORTC_S18: J4.23 MC2.46
PORTC_S19: J4.24 MC2.44
PORTC_S20: J4.25 MC2.50
PORTC_S21: J4.26 MC2.48
PORTC_S22: J4.27 MC2.53
PORTC_S23: J4.28 MC2.43
PORTC_S24: J4.29 MC2.49
PORTC_S25: J4.30 MC2.52
PORTC_S26: J4.31 MC2.51
PORTC_S27: J4.32 MC2.54
PORTD_C2P_CLKN: J5.36 MC2.110
PORTD_C2P_CLKP: J5.34 MC2.108
PORTD_P2C_CLKN: J5.35 MC2.89
PORTD_P2C_CLKP: J5.33 MC2.87
PORTD_S0_D0P: J5.5 MC2.83
PORTD_S1_D1P: J5.6 MC2.79
PORTD_S2_D0N: J5.7 MC2.85
PORTD_S3_D1N: J5.8 MC2.81
PORTD_S4_D2P: J5.9 MC2.80
PORTD_S5_D3P: J5.10 MC2.91
PORTD_S6_D2N: J5.11 MC2.82
PORTD_S7_D3N: J5.12 MC2.93
PORTD_S8_D4P: J5.13 MC2.88
PORTD_S9_D5P: J5.14 MC2.84
PORTD_S10_D4N: J5.15 MC2.90
PORTD_S11_D5N: J5.16 MC2.86
PORTD_S12_D6P: J5.17 MC2.92
PORTD_S13_D7P: J5.18 MC2.95
PORTD_S14_D6N: J5.19 MC2.94
PORTD_S15_D7N: J5.20 MC2.97
PORTD_S16: J5.21 MC2.98
PORTD_S17: J5.22 MC2.96
PORTD_S18: J5.23 MC2.102
PORTD_S19: J5.24 MC2.100
PORTD_S20: J5.25 MC2.105
PORTD_S21: J5.26 MC2.99
PORTD_S22: J5.27 MC2.107
PORTD_S23: J5.28 MC2.106
PORTD_S24: J5.29 MC2.103
PORTD_S25: J5.30 MC2.101
PORTD_S26: J5.31 MC2.109
PORTD_S27: J5.32 MC2.104
PORTE_C2P_CLKN: MC2.156 ; port SZG_PORTE.PORT_C2P_CLKN
PORTE_C2P_CLKP: MC2.154 ; port SZG_PORTE.PORT_C2P_CLKP
PORTE_P2C_CLKN: MC2.150 ; port SZG_PORTE.PORT_P2C_CLKN
PORTE_P2C_CLKP: MC2.148 ; port SZG_PORTE.PORT_P2C_CLKP
PORTE_S0: MC2.137 ; port SZG_PORTE.PORT_S0
PORTE_S1: MC2.143 ; port SZG_PORTE.PORT_S1
PORTE_S2: MC2.140 ; port SZG_PORTE.PORT_S2
PORTE_S3: MC2.145 ; port SZG_PORTE.PORT_S3
PORTE_S4: MC2.138 ; port SZG_PORTE.PORT_S4
PORTE_S5: MC2.147 ; port SZG_PORTE.PORT_S5
PORTE_S6: MC2.136 ; port SZG_PORTE.PORT_S6
PORTE_S7: MC2.142 ; port SZG_PORTE.PORT_S7
PORTE_S8: MC2.153 ; port SZG_PORTE.PORT_S8
PORTE_S9: MC2.151 ; port SZG_PORTE.PORT_S9
PORTF_C2P_CLKN: MC2.171 ; port SZG_PORTF.PORT_C2P_CLKN
PORTF_C2P_CLKP: MC2.169 ; port SZG_PORTF.PORT_C2P_CLKP
PORTF_P2C_CLKN: MC2.164 ; port SZG_PORTF.PORT_P2C_CLKN
PORTF_P2C_CLKP: MC2.162 ; port SZG_PORTF.PORT_P2C_CLKP
PORTF_S0: MC2.180 ; port SZG_PORTF.PORT_S0
PORTF_S1: MC2.178 ; port SZG_PORTF.PORT_S1
PORTF_S2: MC2.160 ; port SZG_PORTF.PORT_S2
PORTF_S3: MC2.159 ; port SZG_PORTF.PORT_S3
PORTF_S4: MC2.158 ; port SZG_PORTF.PORT_S4
PORTF_S5: MC2.161 ; port SZG_PORTF.PORT_S5
PORTF_S6: MC2.170 ; port SZG_PORTF.PORT_S6
PORTF_S7: MC2.173 ; port SZG_PORTF.PORT_S7
PORTF_S8: MC2.172 ; port SZG_PORTF.PORT_S8
PORTF_S9: MC2.175 ; port SZG_PORTF.PORT_S9
QSFP_1_INT_B: MC2.129 ; port QSFP1_Control.IntL
QSFP_1_LP_MODE: MC2.125 ; port QSFP1_Control.LPMode
QSFP_1_MODPRS_B: MC2.126 ; port QSFP1_Control.ModPrsL
QSFP_1_MODSEL_B: MC2.122 ; port QSFP1_Control.ModselL
QSFP_1_RESET_B: MC2.124 ; port QSFP1_Control.ResetL
QSFP_1_SCL: MC2.123 ; port QSFP1_Control.SCL
QSFP_1_SDA: MC2.121 ; port QSFP1_Control.SDA
QSFP_2_INT_B: MC2.127 ; port QSFP2_Control.IntL
QSFP_2_LP_MODE: MC2.128 ; port QSFP2_Control.LPMode
QSFP_2_MODPRS_B: MC2.134 ; port QSFP2_Control.ModPrsL
QSFP_2_MODSEL_B: MC2.130 ; port QSFP2_Control.ModselL
QSFP_2_RESET_B: MC2.132 ; port QSFP2_Control.ResetL
QSFP_2_SCL: MC2.131 ; port QSFP2_Control.SCL
QSFP_2_SDA: MC2.133 ; port QSFP2_Control.SDA
NetJ4_4: J4.4 R9.2
NetJ5_4: J5.4 R10.2

Not connected (* = marked no-connect by the designer): J4 37* 38*; J5 37* 38*; MC2 24* 26* 135* 139* 141* 144* 146* 149* 152* 155* 157* 163* 165* 166* 167* 168* 174* 176* 177* 179*; MH13 1*; MH14 1*; MH15 1*; MH16 1*

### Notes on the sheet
- Mezzanine Connector MC2
- SYZYGY PORT C (VIO2)
- Address 0x32
- SYZYGY PORT D (VIO2)
- Address 0x33
- MOUNTING HOLES
- 2mm Headers
- SYZYGY PORT E
- SYZYGY PORT F
- Title
- Size:
- Date:
- File:
- C
- Number:
- Time:
- Revision:
- Sheet
- of

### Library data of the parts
J4 J5 = 001604: 0.8mm hi-speed, high-density header (male); Manufacturer: Samtec; partnumber: 001604; Description 2: 40-pin, ground protection in middle; x_lifecycle_status: Production
MC2 = 000876: 0.5mm Double Row High Speed Socket Assembly; Partnumber: 000876; manufacturer: Samtec; id: 17471; inventory_price: 8.87
MC2A = 000583: Partnumber: 000583; manufacturer: Molex; id: 9990; inventory_price: 1.03
MC2B = 001334: PartNumber: 001334; manufacturer: 3M; manufacturer_pn: 951120-8622-AR; id: 98023; inventory_price: 0.924
MH13-MH16 = MTG: Mounting hole; partnumber: ALIGNI_IGNORE
R9 = Resistor: Thick-film resistor; manufacturer: Yageo; partnumber: 001908; ValueFloat: 8870.0
R10 = Resistor: Thick-film resistor; manufacturer: Yageo; partnumber: 001909; ValueFloat: 6980.0

## Sheet MC1.SchDoc: BRK8350 - Mezzanine Connector MC1
size C; Author: Casey Smith; Organization: Opal Kelly; Address1: 13500 SW 72nd Ave STE 100; Address2: Portland, OR 97223; Address3: 217.391.3724; Address4: http://www.opalkelly.com; DocumentNumber: xxx; Revision: 1; SheetNumber: 2; SheetTotal: 7
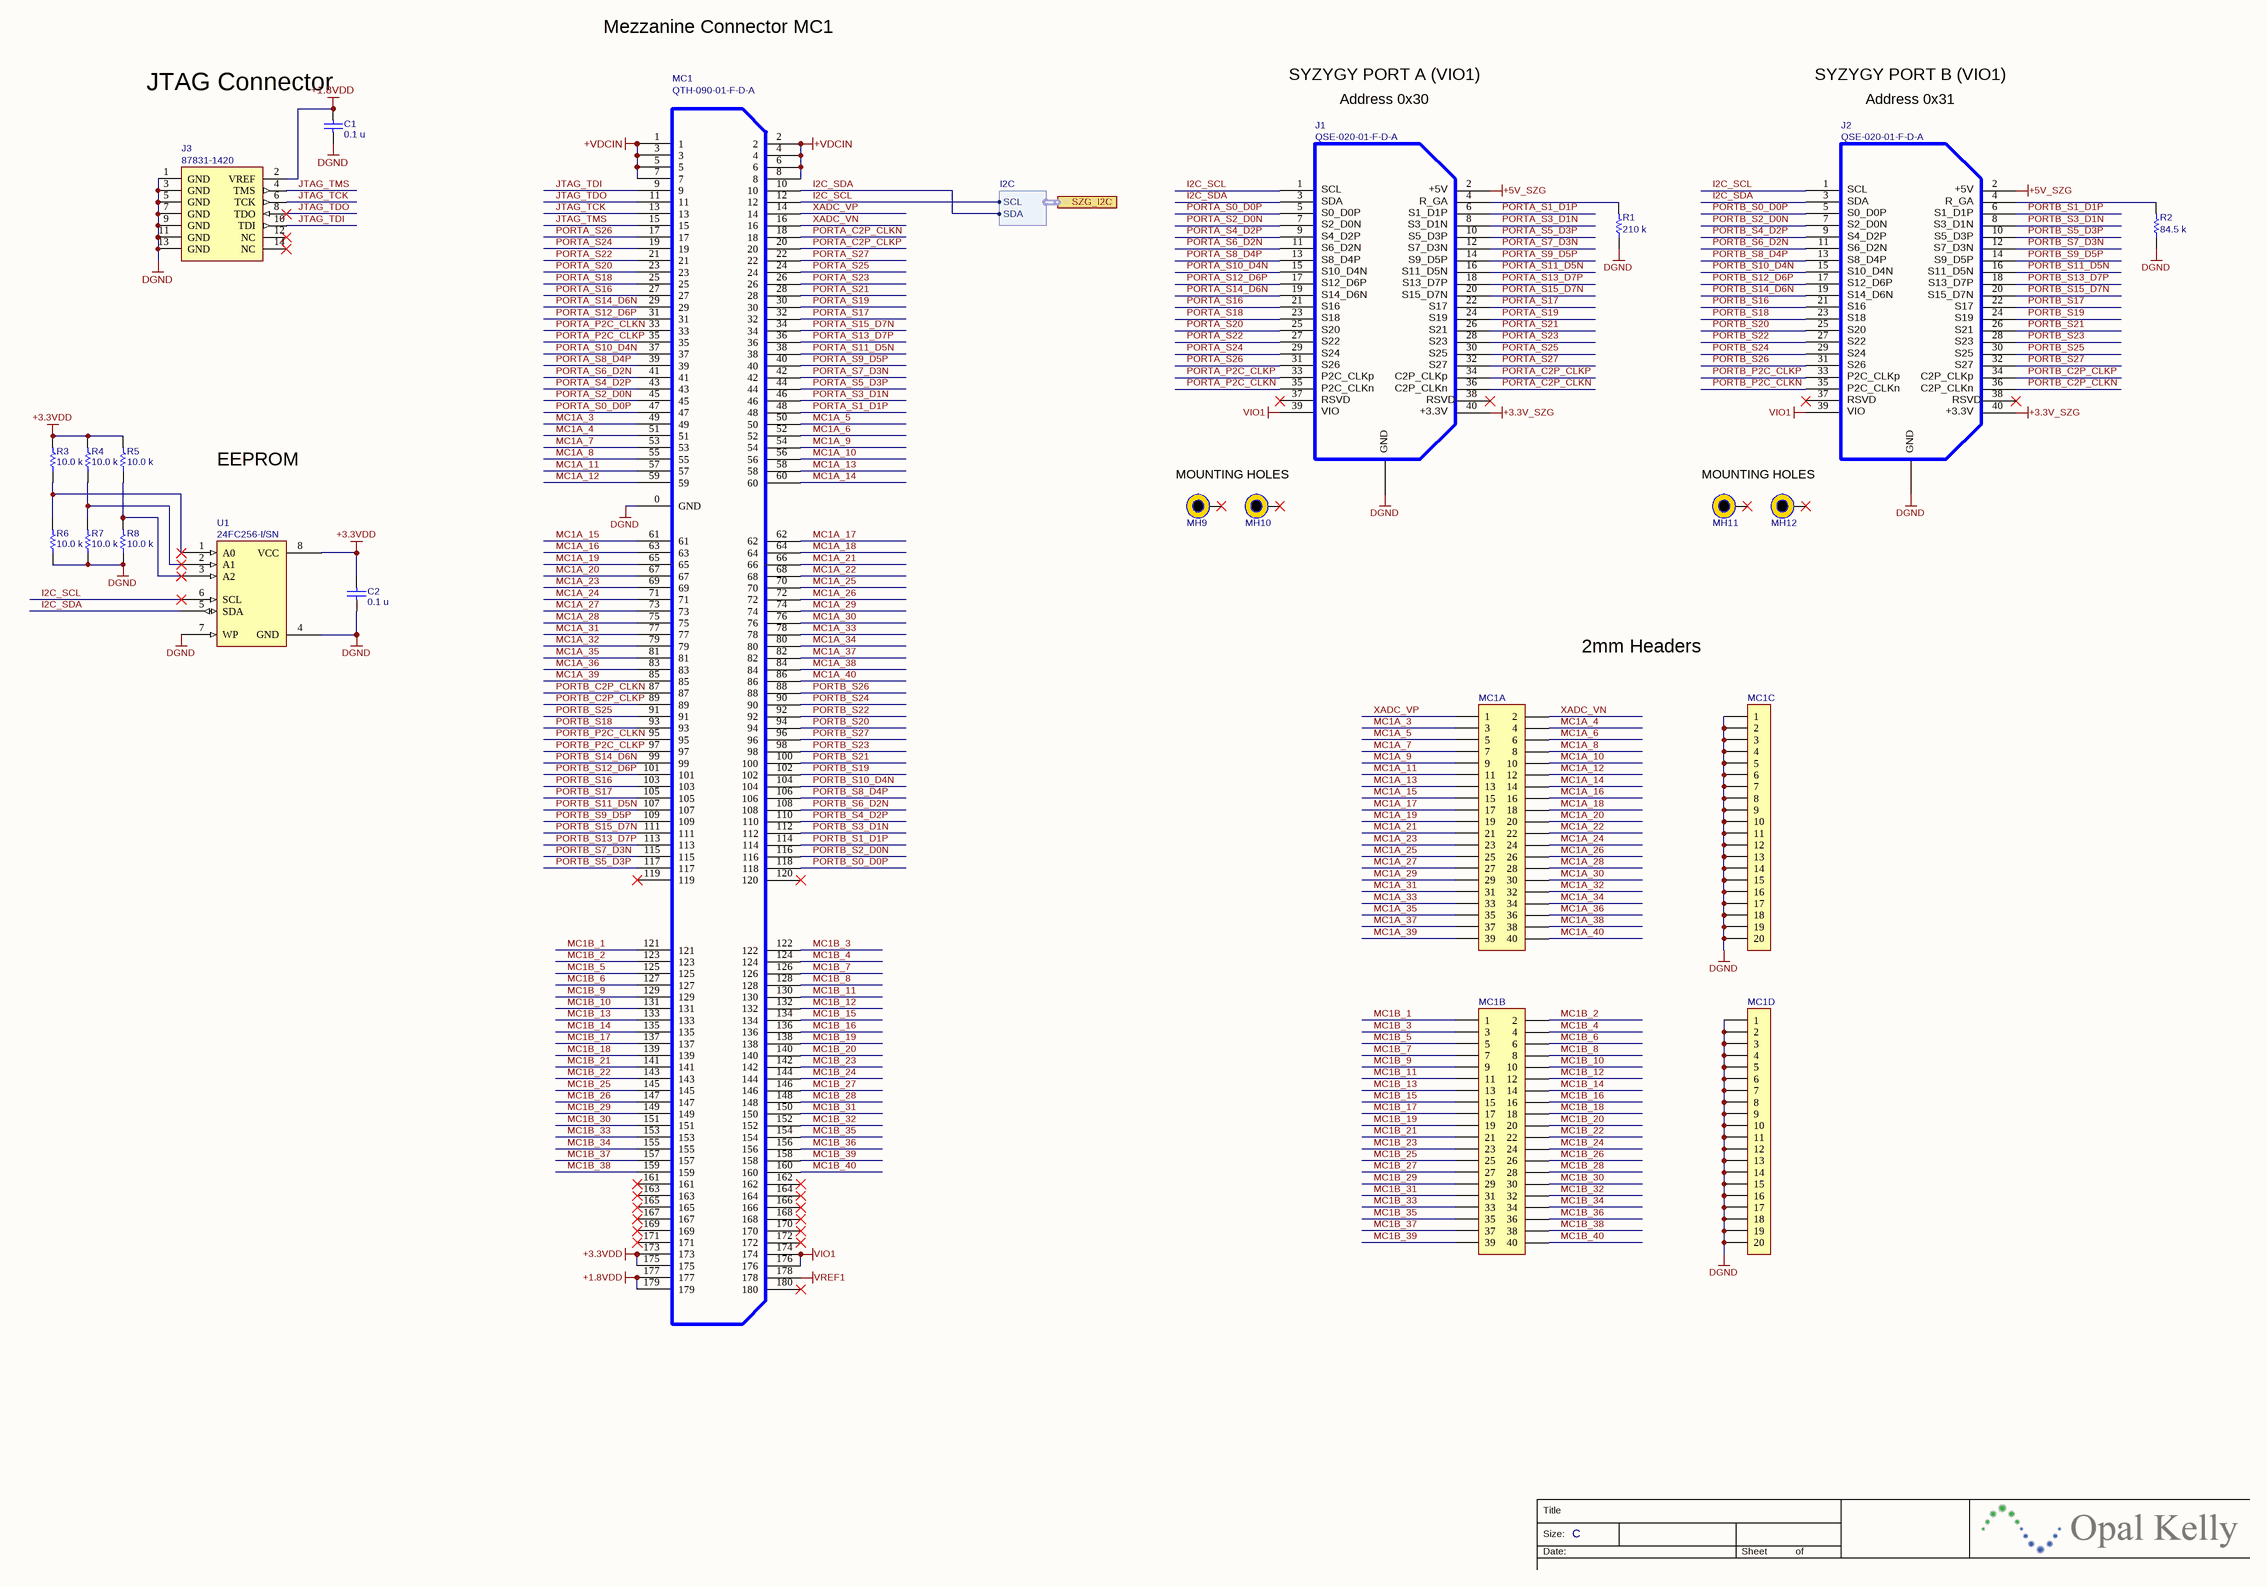
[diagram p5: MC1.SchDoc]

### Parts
C1  value 0.1 u  [CAPC1005X06A]  (hidden comment: SM-0402, 10%, 10v)
C2  value 0.1 u  [CAPC1005X06A]  (hidden comment: SM-0402, 10%, 10v)
J1  QSE-020-01-F-D-A  [QSE-020-01-X-D-A-L]
J2  QSE-020-01-F-D-A  [QSE-020-01-X-D-A-L]
J3  87831-1420  [XILINX-JTAG]
MC1  QTH-090-01-F-D-A  [QTH-090-01-X-D]
MC1A  0877584016  [HDR2X20-2MM]  (value not drawn)
MC1B  0877584016  [HDR2X20-2MM]  (value not drawn)
MC1C  Header, 20-Pin, Single Row  [HDR1X20-2MM]  (value not drawn)
MC1D  Header, 20-Pin, Single Row  [HDR1X20-2MM]  (value not drawn)
MH9  MTG  [MTG-3.2/6.5-PTH]  (value not drawn)
MH10  MTG  [MTG-3.2/6.5-PTH]  (value not drawn)
MH11  MTG  [MTG-3.2/6.5-PTH]  (value not drawn)
MH12  MTG  [MTG-3.2/6.5-PTH]  (value not drawn)
R1  value 210 k  [RESC1005X06A]  (hidden comment: CRCW0402210KFKED)
R2  value 84.5 k  [RESC1005X06A]  (hidden comment: CRCW040284K5FKED)
R3  value 10.0 k  [RESC1005X06A]  (hidden comment: SM-0402, 1%, 1/16W)
R4  value 10.0 k  [RESC1005X06A]  (hidden comment: SM-0402, 1%, 1/16W)
R5  value 10.0 k  [RESC1005X06A]  (hidden comment: SM-0402, 1%, 1/16W)
R6  value 10.0 k  [RESC1005X06A]  (hidden comment: SM-0402, 1%, 1/16W)
R7  value 10.0 k  [RESC1005X06A]  (hidden comment: SM-0402, 1%, 1/16W)
R8  value 10.0 k  [RESC1005X06A]  (hidden comment: SM-0402, 1%, 1/16W)
U1  24FC256-I/SN  [SO-G8]

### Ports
SZG_I2C (harness I2C)

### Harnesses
I2C: SCL, SDA

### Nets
+1.8VDD: C1.2 J3.2(VREF) MC1.177 MC1.179
+3.3V_SZG: J1.40 J2.40
+3.3VDD: C2.2 MC1.173 MC1.175 R3.2 R4.2 R5.2 U1.8(VCC)
+5V_SZG: J1.2 J2.2
+VDCIN: MC1.1 MC1.2 MC1.3 MC1.4 MC1.5 MC1.6 MC1.7 MC1.8
DGND: C1.1 C2.1 J1.0 J2.0 J3.1(GND) J3.3(GND) J3.5(GND) J3.7(GND) J3.9(GND) J3.11(GND) J3.13(GND) MC1.0(GND) MC1C.1 MC1C.2 MC1C.3 MC1C.4 MC1C.5 MC1C.6 MC1C.7 MC1C.8 MC1C.9 MC1C.10 MC1C.11 MC1C.12 MC1C.13 MC1C.14 MC1C.15 MC1C.16 MC1C.17 MC1C.18 MC1C.19 MC1C.20 MC1D.1 MC1D.2 MC1D.3 MC1D.4 MC1D.5 MC1D.6 MC1D.7 MC1D.8 MC1D.9 MC1D.10 MC1D.11 MC1D.12 MC1D.13 MC1D.14 MC1D.15 MC1D.16 MC1D.17 MC1D.18 MC1D.19 MC1D.20 R1.1 R2.1 R6.1 R7.1 R8.1 U1.4(GND) U1.7(WP)
VIO1: J1.39 J2.39 MC1.174 MC1.176
VREF1: MC1.178
I2C_SCL: J1.1 J2.1 MC1.12 U1.6(SCL) ; port SZG_I2C.SCL
I2C_SDA: J1.3 J2.3 MC1.10 U1.5(SDA) ; port SZG_I2C.SDA
JTAG_TCK: J3.6(TCK) MC1.13
JTAG_TDI: J3.10(TDI) MC1.9
JTAG_TDO: J3.8(TDO) MC1.11
JTAG_TMS: J3.4(TMS) MC1.15
MC1A_3: MC1.49 MC1A.3
MC1A_4: MC1.51 MC1A.4
MC1A_5: MC1.50 MC1A.5
MC1A_6: MC1.52 MC1A.6
MC1A_7: MC1.53 MC1A.7
MC1A_8: MC1.55 MC1A.8
MC1A_9: MC1.54 MC1A.9
MC1A_10: MC1.56 MC1A.10
MC1A_11: MC1.57 MC1A.11
MC1A_12: MC1.59 MC1A.12
MC1A_13: MC1.58 MC1A.13
MC1A_14: MC1.60 MC1A.14
MC1A_15: MC1.61 MC1A.15
MC1A_16: MC1.63 MC1A.16
MC1A_17: MC1.62 MC1A.17
MC1A_18: MC1.64 MC1A.18
MC1A_19: MC1.65 MC1A.19
MC1A_20: MC1.67 MC1A.20
MC1A_21: MC1.66 MC1A.21
MC1A_22: MC1.68 MC1A.22
MC1A_23: MC1.69 MC1A.23
MC1A_24: MC1.71 MC1A.24
MC1A_25: MC1.70 MC1A.25
MC1A_26: MC1.72 MC1A.26
MC1A_27: MC1.73 MC1A.27
MC1A_28: MC1.75 MC1A.28
MC1A_29: MC1.74 MC1A.29
MC1A_30: MC1.76 MC1A.30
MC1A_31: MC1.77 MC1A.31
MC1A_32: MC1.79 MC1A.32
MC1A_33: MC1.78 MC1A.33
MC1A_34: MC1.80 MC1A.34
MC1A_35: MC1.81 MC1A.35
MC1A_36: MC1.83 MC1A.36
MC1A_37: MC1.82 MC1A.37
MC1A_38: MC1.84 MC1A.38
MC1A_39: MC1.85 MC1A.39
MC1A_40: MC1.86 MC1A.40
MC1B_1: MC1.121 MC1B.1
MC1B_2: MC1.123 MC1B.2
MC1B_3: MC1.122 MC1B.3
MC1B_4: MC1.124 MC1B.4
MC1B_5: MC1.125 MC1B.5
MC1B_6: MC1.127 MC1B.6
MC1B_7: MC1.126 MC1B.7
MC1B_8: MC1.128 MC1B.8
MC1B_9: MC1.129 MC1B.9
MC1B_10: MC1.131 MC1B.10
MC1B_11: MC1.130 MC1B.11
MC1B_12: MC1.132 MC1B.12
MC1B_13: MC1.133 MC1B.13
MC1B_14: MC1.135 MC1B.14
MC1B_15: MC1.134 MC1B.15
MC1B_16: MC1.136 MC1B.16
MC1B_17: MC1.137 MC1B.17
MC1B_18: MC1.139 MC1B.18
MC1B_19: MC1.138 MC1B.19
MC1B_20: MC1.140 MC1B.20
MC1B_21: MC1.141 MC1B.21
MC1B_22: MC1.143 MC1B.22
MC1B_23: MC1.142 MC1B.23
MC1B_24: MC1.144 MC1B.24
MC1B_25: MC1.145 MC1B.25
MC1B_26: MC1.147 MC1B.26
MC1B_27: MC1.146 MC1B.27
MC1B_28: MC1.148 MC1B.28
MC1B_29: MC1.149 MC1B.29
MC1B_30: MC1.151 MC1B.30
MC1B_31: MC1.150 MC1B.31
MC1B_32: MC1.152 MC1B.32
MC1B_33: MC1.153 MC1B.33
MC1B_34: MC1.155 MC1B.34
MC1B_35: MC1.154 MC1B.35
MC1B_36: MC1.156 MC1B.36
MC1B_37: MC1.157 MC1B.37
MC1B_38: MC1.159 MC1B.38
MC1B_39: MC1.158 MC1B.39
MC1B_40: MC1.160 MC1B.40
PORTA_C2P_CLKN: J1.36 MC1.18
PORTA_C2P_CLKP: J1.34 MC1.20
PORTA_P2C_CLKN: J1.35 MC1.33
PORTA_P2C_CLKP: J1.33 MC1.35
PORTA_S0_D0P: J1.5 MC1.47
PORTA_S1_D1P: J1.6 MC1.48
PORTA_S2_D0N: J1.7 MC1.45
PORTA_S3_D1N: J1.8 MC1.46
PORTA_S4_D2P: J1.9 MC1.43
PORTA_S5_D3P: J1.10 MC1.44
PORTA_S6_D2N: J1.11 MC1.41
PORTA_S7_D3N: J1.12 MC1.42
PORTA_S8_D4P: J1.13 MC1.39
PORTA_S9_D5P: J1.14 MC1.40
PORTA_S10_D4N: J1.15 MC1.37
PORTA_S11_D5N: J1.16 MC1.38
PORTA_S12_D6P: J1.17 MC1.31
PORTA_S13_D7P: J1.18 MC1.36
PORTA_S14_D6N: J1.19 MC1.29
PORTA_S15_D7N: J1.20 MC1.34
PORTA_S16: J1.21 MC1.27
PORTA_S17: J1.22 MC1.32
PORTA_S18: J1.23 MC1.25
PORTA_S19: J1.24 MC1.30
PORTA_S20: J1.25 MC1.23
PORTA_S21: J1.26 MC1.28
PORTA_S22: J1.27 MC1.21
PORTA_S23: J1.28 MC1.26
PORTA_S24: J1.29 MC1.19
PORTA_S25: J1.30 MC1.24
PORTA_S26: J1.31 MC1.17
PORTA_S27: J1.32 MC1.22
PORTB_C2P_CLKN: J2.36 MC1.87
PORTB_C2P_CLKP: J2.34 MC1.89
PORTB_P2C_CLKN: J2.35 MC1.95
PORTB_P2C_CLKP: J2.33 MC1.97
PORTB_S0_D0P: J2.5 MC1.118
PORTB_S1_D1P: J2.6 MC1.114
PORTB_S2_D0N: J2.7 MC1.116
PORTB_S3_D1N: J2.8 MC1.112
PORTB_S4_D2P: J2.9 MC1.110
PORTB_S5_D3P: J2.10 MC1.117
PORTB_S6_D2N: J2.11 MC1.108
PORTB_S7_D3N: J2.12 MC1.115
PORTB_S8_D4P: J2.13 MC1.106
PORTB_S9_D5P: J2.14 MC1.109
PORTB_S10_D4N: J2.15 MC1.104
PORTB_S11_D5N: J2.16 MC1.107
PORTB_S12_D6P: J2.17 MC1.101
PORTB_S13_D7P: J2.18 MC1.113
PORTB_S14_D6N: J2.19 MC1.99
PORTB_S15_D7N: J2.20 MC1.111
PORTB_S16: J2.21 MC1.103
PORTB_S17: J2.22 MC1.105
PORTB_S18: J2.23 MC1.93
PORTB_S19: J2.24 MC1.102
PORTB_S20: J2.25 MC1.94
PORTB_S21: J2.26 MC1.100
PORTB_S22: J2.27 MC1.92
PORTB_S23: J2.28 MC1.98
PORTB_S24: J2.29 MC1.90
PORTB_S25: J2.30 MC1.91
PORTB_S26: J2.31 MC1.88
PORTB_S27: J2.32 MC1.96
XADC_VN: MC1.16 MC1A.2
XADC_VP: MC1.14 MC1A.1
NetJ1_4: J1.4 R1.2
NetJ2_4: J2.4 R2.2
NetR3_1: R3.1 R6.2 U1.1(A0)
NetR4_1: R4.1 R7.2 U1.2(A1)
NetR5_1: R5.1 R8.2 U1.3(A2)

Not connected (* = marked no-connect by the designer): J1 37* 38*; J2 37* 38*; J3 12(NC)* 14(NC)*; MC1 119* 120* 161* 162* 163* 164* 165* 166* 167* 168* 169* 170* 171* 172* 180*; MH9 1*; MH10 1*; MH11 1*; MH12 1*

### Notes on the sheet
- Mezzanine Connector MC1
- (near C1) JTAG Connector
- SYZYGY PORT A (VIO1)
- Address 0x30
- SYZYGY PORT B (VIO1)
- Address 0x31
- EEPROM
- MOUNTING HOLES
- 2mm Headers
- Title
- Size:
- Date:
- C
- Sheet
- of

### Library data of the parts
C1 = 000070: as C90 on sheet Transceiver-QSFP
C2 = 000070: Partnumber: 000070; manufacturer: Kemet; manufacturer_pn: C0402C104K8PACTU; ValueFloat: 1E-7; id: 750; inventory_price: 0.0023; reorder_quantity: 70000; x_max_operating_temp: 85; x_min_operating_temp: -55; x_tolerance: 10
J1 J2 = 001604: as J4 on sheet MC2
J3 = 000541: 2mm header, shrouded; Manufacturer: Molex; partnumber: 000541; Description 2: Dual-row, 14-pos, Xilinx JTAG compatible
MC1 = 000876: as MC2 on sheet MC2
MC1A MC1B = 000583: as MC2A on sheet MC2
MC1C MC1D = 001334: as MC2B on sheet MC2
MH9-MH12 = MTG: Mounting hole; partnumber: ALIGNI_IGNORE
R1 = 001549: Thick-film resistor; Manufacturer: Vishay; partnumber: 001549; Description 2: SM-0402, 1%, 1/16W; ValueFloat: 210000; Tolerance (%): 1; x_lifecycle_status: Production
R2 = 001550: Thick-film resistor; Manufacturer: Vishay; partnumber: 001550; Description 2: SM-0402, 1%, 1/16W; ValueFloat: 84500; Tolerance (%): 1; x_lifecycle_status: Production
R3-R8 = 001521: Partnumber: 001521; manufacturer: Vishay; manufacturer_pn: CRCW040210K0FKED; ValueFloat: 10000; id: 154248; inventory_price: 0.0016; x_tolerance: 1
U1 = 000842: Partnumber: 000842; manufacturer: Microchip; id: 14766; inventory_price: 0.39; reorder_quantity: 600

## Sheet Power.SchDoc: BRK8350 - Power
size C; Organization: Opal Kelly; Address1: 13500 SW 72nd Ave STE 100; Address3: Portland, OR  97223; Address4: http://www.opalkelly.com; DocumentNumber: xxx; Revision: 1; SheetNumber: 7; SheetTotal: 7; PageSetup: Record=PageOptions¦CenterHorizontal=True¦CenterVertical=True¦PrintScale=0.52¦XCorrection=1.00¦YCorrection=1.00¦PrintKind=0¦BorderSize=5000000¦LeftOffset=0¦BottomOffset=0¦Orientation=2¦PaperLength=1000¦PaperWidth=1000¦Scale=100¦PaperSource=15¦PrintQuality=600¦MediaType=1¦DitherType=10¦PaperKind=Letter¦PrintScaleMode=1
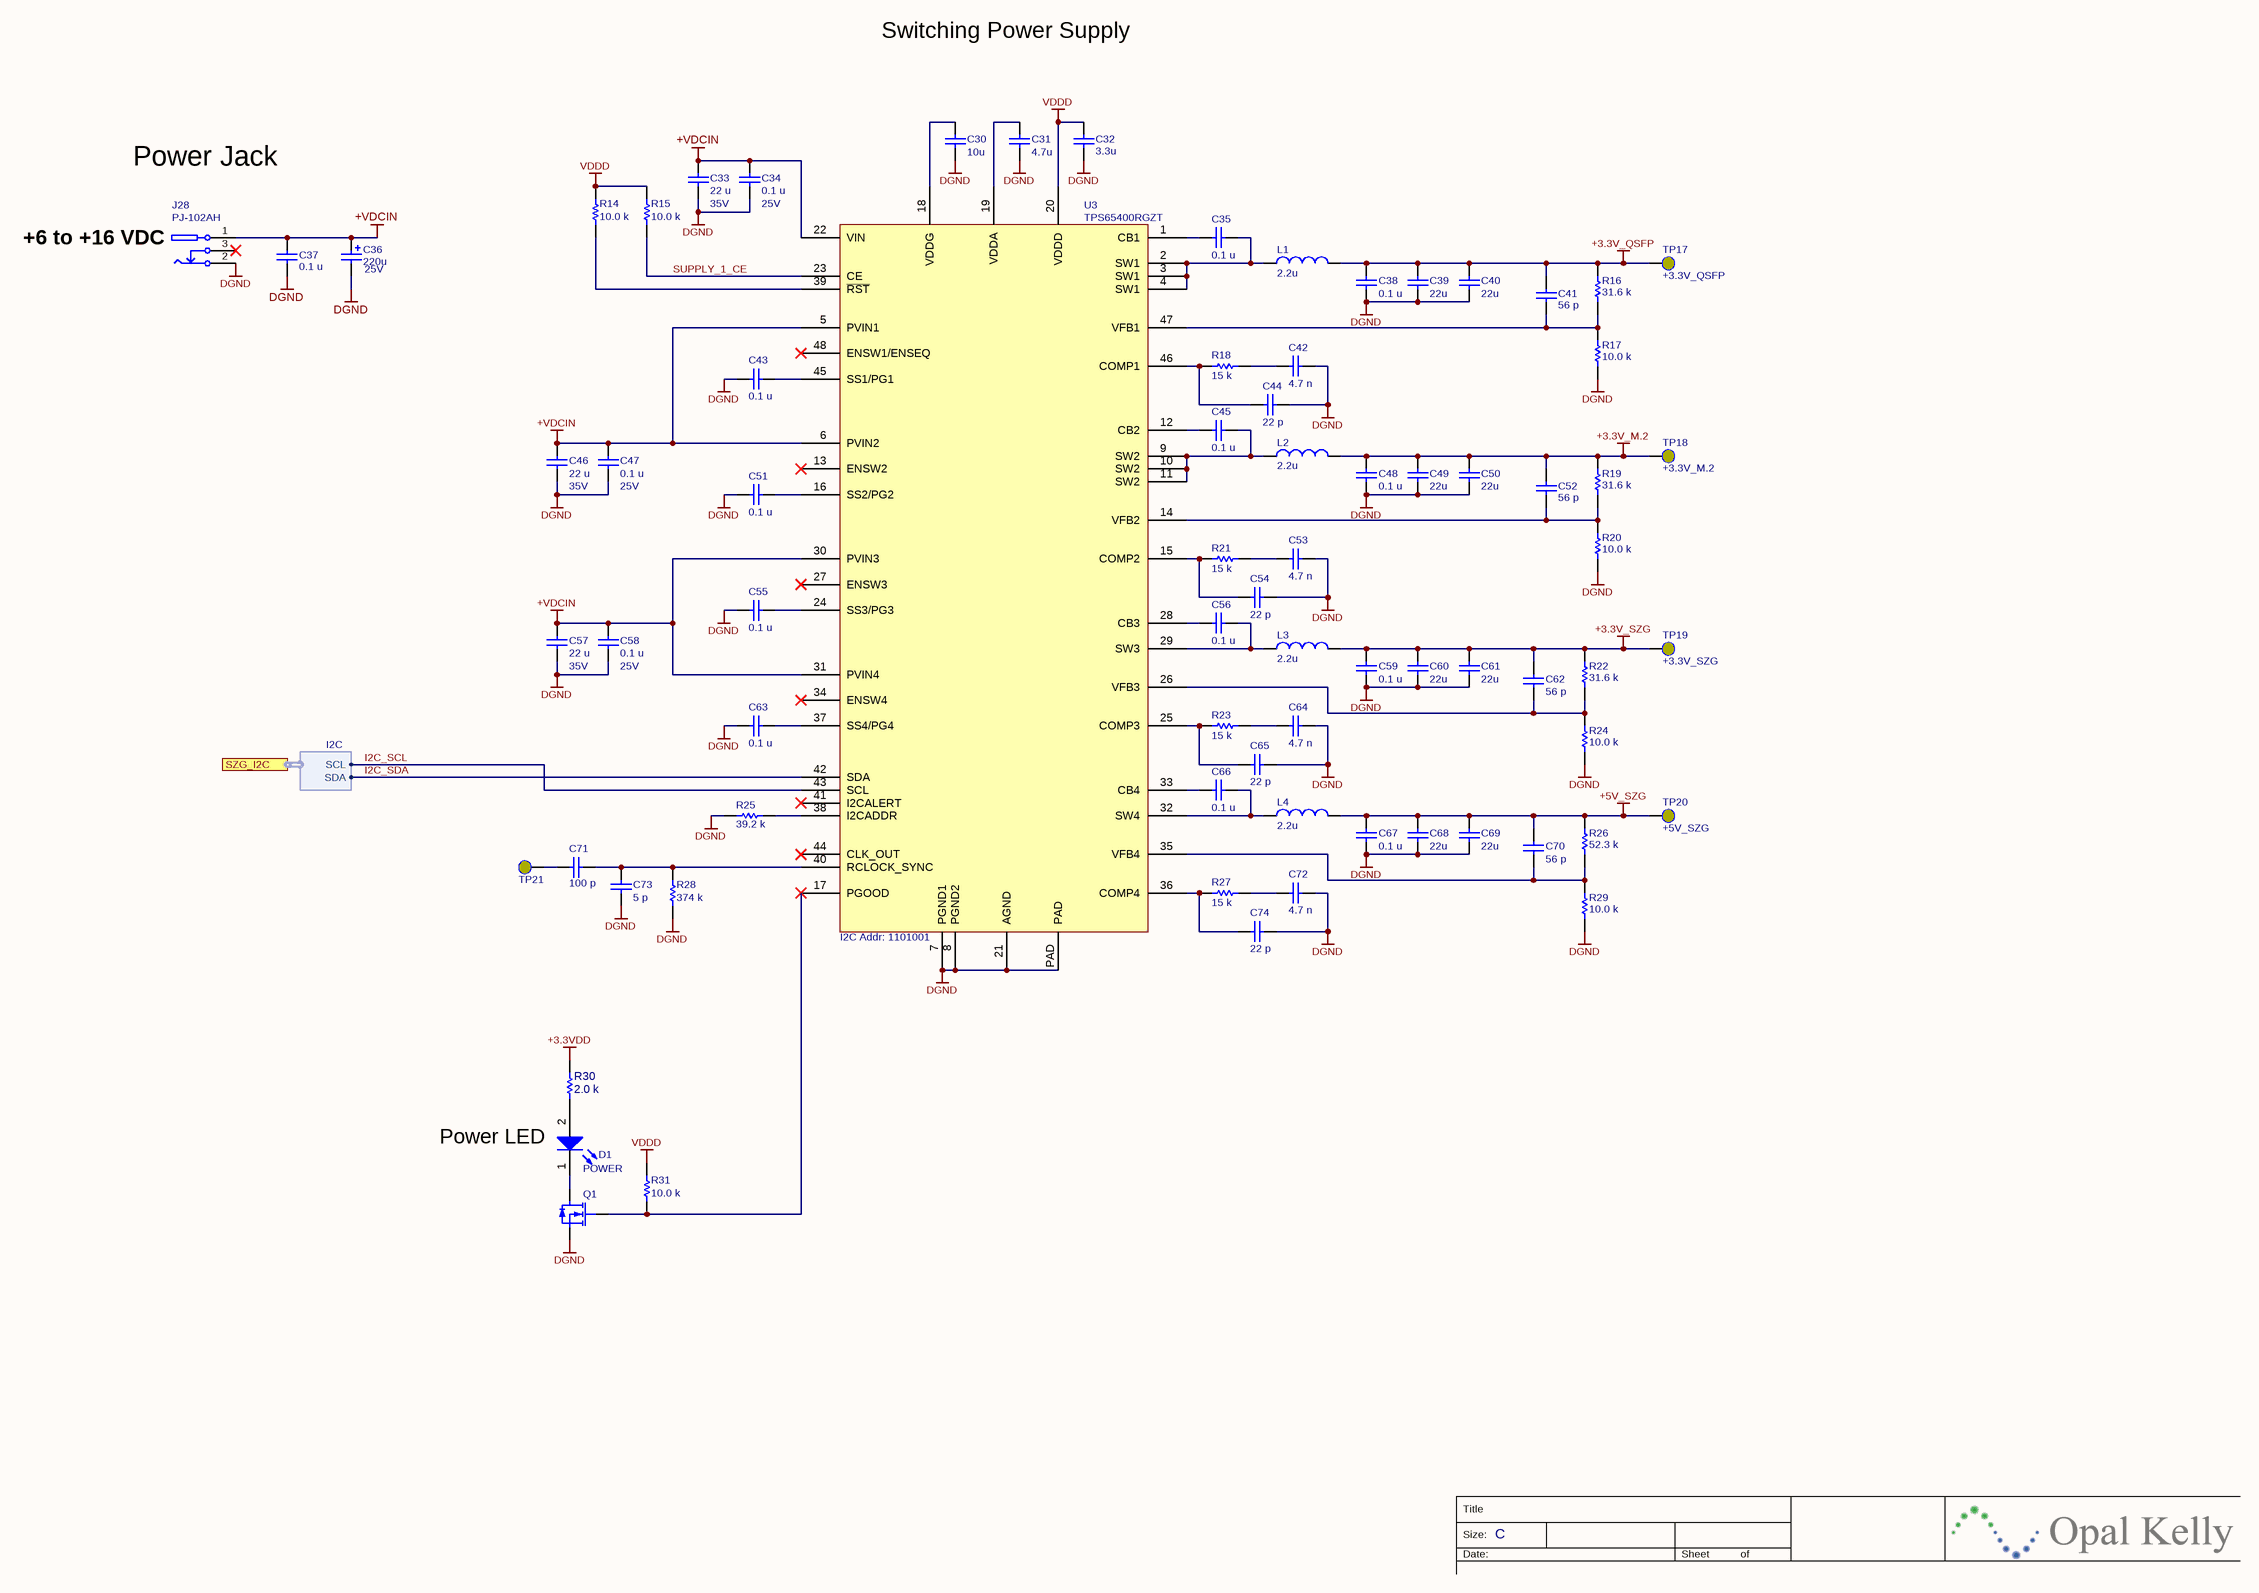
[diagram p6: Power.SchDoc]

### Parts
C30  value 10u  [CAPC1608N]  (hidden comment: LMK107BJ106MALTD)
C31  value 4.7u  [CAPC1005X06A]  (hidden comment: JMK105BBJ475MV-F)
C32  value 3.3u  [CAPC1005X06A]  (hidden comment: C1005X5R1A335K050BC)
C33  value 22 u  Voltage: 35V  [CAPC3216N]  (hidden comment: C3216X5R1V226M160AC)
C34  value 0.1 u  Voltage: 25V  [CAPC1005X06A]  (hidden comment: TMK105BJ104KV-F)
C35  value 0.1 u  [CAPC1005X06A]  (hidden comment: C0402C104K8PACTU)
C36  value 220u  Voltage: 25V  [CAPAE9083X70N]  (hidden comment: EEE-FK1E221P)
C37  value 0.1 u  [CAPC1005X06A]  (hidden comment: TMK105BJ104KV-F)
C38  value 0.1 u  [CAPC1005X06A]  (hidden comment: C0402C104K8PACTU)
C39  value 22u  [CAPC3216N]  (hidden comment: LMK316AB7226KL-TR)
C40  value 22u  [CAPC3216N]  (hidden comment: LMK316AB7226KL-TR)
C41  value 56 p  [CAPC1005X06A]  (hidden comment: SM-0402, 5%, 50v)
C42  value 4.7 n  [CAPC1005X06A]  (hidden comment: C0402C472K5RACTU)
C43  value 0.1 u  [CAPC1005X06A]  (hidden comment: C0402C104K8PACTU)
C44  value 22 p  [CAPC1005X06A]  (hidden comment: C0402C220J5GACTU)
C45  value 0.1 u  [CAPC1005X06A]  (hidden comment: C0402C104K8PACTU)
C46  value 22 u  Voltage: 35V  [CAPC3216N]  (hidden comment: C3216X5R1V226M160AC)
C47  value 0.1 u  Voltage: 25V  [CAPC1005X06A]  (hidden comment: TMK105BJ104KV-F)
C48  value 0.1 u  [CAPC1005X06A]  (hidden comment: C0402C104K8PACTU)
C49  value 22u  [CAPC3216N]  (hidden comment: LMK316AB7226KL-TR)
C50  value 22u  [CAPC3216N]  (hidden comment: LMK316AB7226KL-TR)
C51  value 0.1 u  [CAPC1005X06A]  (hidden comment: C0402C104K8PACTU)
C52  value 56 p  [CAPC1005X06A]  (hidden comment: SM-0402, 5%, 50v)
C53  value 4.7 n  [CAPC1005X06A]  (hidden comment: C0402C472K5RACTU)
C54  value 22 p  [CAPC1005X06A]  (hidden comment: C0402C220J5GACTU)
C55  value 0.1 u  [CAPC1005X06A]  (hidden comment: C0402C104K8PACTU)
C56  value 0.1 u  [CAPC1005X06A]  (hidden comment: C0402C104K8PACTU)
C57  value 22 u  Voltage: 35V  [CAPC3216N]  (hidden comment: C3216X5R1V226M160AC)
C58  value 0.1 u  Voltage: 25V  [CAPC1005X06A]  (hidden comment: TMK105BJ104KV-F)
C59  value 0.1 u  [CAPC1005X06A]  (hidden comment: C0402C104K8PACTU)
C60  value 22u  [CAPC3216N]  (hidden comment: LMK316AB7226KL-TR)
C61  value 22u  [CAPC3216N]  (hidden comment: LMK316AB7226KL-TR)
C62  value 56 p  [CAPC1005X06A]  (hidden comment: C0402C560J5GACTU)
C63  value 0.1 u  [CAPC1005X06A]  (hidden comment: C0402C104K8PACTU)
C64  value 4.7 n  [CAPC1005X06A]  (hidden comment: C0402C472K5RACTU)
C65  value 22 p  [CAPC1005X06A]  (hidden comment: C0402C220J5GACTU)
C66  value 0.1 u  [CAPC1005X06A]  (hidden comment: C0402C104K8PACTU)
C67  value 0.1 u  [CAPC1005X06A]  (hidden comment: C0402C104K8PACTU)
C68  value 22u  [CAPC3216N]  (hidden comment: LMK316AB7226KL-TR)
C69  value 22u  [CAPC3216N]  (hidden comment: LMK316AB7226KL-TR)
C70  value 56 p  [CAPC1005X06A]  (hidden comment: C0402C560J5GACTU)
C71  value 100 p  [CAPC1005X06A]  (hidden comment: SM-0402, 5%, 50V, NP0)
C72  value 4.7 n  [CAPC1005X06A]  (hidden comment: C0402C472K5RACTU)
C73  value 5 p  [CAPC1005X06A]  (hidden comment: GJM1555C1H5R0CB01D)
C74  value 22 p  [CAPC1005X06A]  (hidden comment: C0402C220J5GACTU)
D1  POWER  [CD1608-0603-PIN1-CATHODE]
J28  PJ-102AH  [CUI-PJ102A]
L1  value 2.2u  [XAL60XX]  (hidden comment: XAL6030-222MEB)
L2  value 2.2u  [XAL60XX]  (hidden comment: XAL6030-222MEB)
L3  value 2.2u  [XAL60XX]  (hidden comment: XAL6030-222MEB)
L4  value 2.2u  [XAL60XX]  (hidden comment: XAL6030-222MEB)
Q1  2.2A, 30V  [SOT23-95P240X110]  (value not drawn)
R14  value 10.0 k  [RESC1005X06A]  (hidden comment: CRCW040210K0FKED)
R15  value 10.0 k  [RESC1005X06A]  (hidden comment: CRCW040210K0FKED)
R16  value 31.6 k  [RESC1005X06A]  (hidden comment: SM-0402, 1%, 1/16W)
R17  value 10.0 k  [RESC1005X06A]  (hidden comment: SM-0402, 1%, 1/16W)
R18  value 15 k  [RESC1005X06A]  (hidden comment: CRCW040215K0FKED)
R19  value 31.6 k  [RESC1005X06A]  (hidden comment: SM-0402, 1%, 1/16W)
R20  value 10.0 k  [RESC1005X06A]  (hidden comment: SM-0402, 1%, 1/16W)
R21  value 15 k  [RESC1005X06A]  (hidden comment: CRCW040215K0FKED)
R22  value 31.6 k  [RESC1005X06A]  (hidden comment: SM-0402, 1%, 1/16W)
R23  value 15 k  [RESC1005X06A]  (hidden comment: CRCW040215K0FKED)
R24  value 10.0 k  [RESC1005X06A]  (hidden comment: SM-0402, 1%, 1/16W)
R25  value 39.2 k  [RESC1005X06A]  (hidden comment: CRCW040239K2FKED)
R26  value 52.3 k  [RESC1005X06A]  (hidden comment: SM-0402, 1%, 1/16W)
R27  value 15 k  [RESC1005X06A]  (hidden comment: CRCW040215K0FKED)
R28  value 374 k  [RESC1005X06A]  (hidden comment: CRCW0402374KFKED)
R29  value 10.0 k  [RESC1005X06A]  (hidden comment: SM-0402, 1%, 1/16W)
R30  value 2.0 k  [RESC1005X06A]  (hidden comment: CRCW04022K00FKED)
R31  value 10.0 k  [RESC1005X06A]  (hidden comment: CRCW040210K0FKED)
TP17  +3.3V_QSFP  [TP-SMD40]
TP18  +3.3V_M.2  [TP-SMD40]
TP19  +3.3V_SZG  [TP-SMD40]
TP20  +5V_SZG  [TP-SMD40]
TP21  TESTPOINT-SMD40  [TP-SMD40]  (value not drawn)
U3  TPS65400RGZT  [PVQFN-48]

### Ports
SZG_I2C (harness I2C)

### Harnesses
I2C: SCL, SDA

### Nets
+3.3V_M.2: C48.2 C49.2 C50.2 C52.2 L2.2 R19.2 TP18.1(PIN)
+3.3V_QSFP: C38.2 C39.2 C40.2 C41.2 L1.2 R16.2 TP17.1(PIN)
+3.3V_SZG: C59.2 C60.2 C61.2 C62.2 L3.2 R22.2 TP19.1(PIN)
+3.3VDD: R30.2
+5V_SZG: C67.2 C68.2 C69.2 C70.2 L4.2 R26.2 TP20.1(PIN)
+VDCIN: C33.1 C34.1 C36.1 C37.2 C46.1 C47.1 C57.1 C58.1 J28.1 U3.5(PVIN1) U3.6(PVIN2) U3.22(VIN) U3.30(PVIN3) U3.31(PVIN4)
DGND: C30.1 C31.1 C32.1 C33.2 C34.2 C36.2 C37.1 C38.1 C39.1 C40.1 C42.2 C43.2 C44.2 C46.2 C47.2 C48.1 C49.1 C50.1 C51.1 C53.2 C54.2 C55.2 C57.2 C58.2 C59.1 C60.1 C61.1 C63.2 C64.2 C65.2 C67.1 C68.1 C69.1 C72.2 C73.1 C74.2 J28.2 Q1.2(S) R17.1 R20.1 R24.1 R25.1 R28.1 R29.1 U3.7(PGND1) U3.8(PGND2) U3.21(AGND) U3.PAD
VDDD: C32.2 R14.2 R15.2 R31.2 U3.20(VDDD)
I2C_SCL: U3.43(SCL) ; port SZG_I2C.SCL
I2C_SDA: U3.42(SDA) ; port SZG_I2C.SDA
SUPPLY_1_CE: R15.1 U3.23(CE)
NetC30_2: C30.2 U3.18(VDDG)
NetC31_2: C31.2 U3.19(VDDA)
NetC35_1: C35.1 U3.1(CB1)
NetC35_2: C35.2 L1.1 U3.2(SW1) U3.3(SW1) U3.4(SW1)
NetC41_1: C41.1 R16.1 R17.2 U3.47(VFB1)
NetC42_1: C42.1 R18.2
NetC43_1: C43.1 U3.45(SS1/PG1)
NetC44_1: C44.1 R18.1 U3.46(COMP1)
NetC45_1: C45.1 U3.12(CB2)
NetC45_2: C45.2 L2.1 U3.9(SW2) U3.10(SW2) U3.11(SW2)
NetC51_2: C51.2 U3.16(SS2/PG2)
NetC52_1: C52.1 R19.1 R20.2 U3.14(VFB2)
NetC53_1: C53.1 R21.2
NetC54_1: C54.1 R21.1 U3.15(COMP2)
NetC55_1: C55.1 U3.24(SS3/PG3)
NetC56_1: C56.1 U3.28(CB3)
NetC56_2: C56.2 L3.1 U3.29(SW3)
NetC62_1: C62.1 R22.1 R24.2 U3.26(VFB3)
NetC63_1: C63.1 U3.37(SS4/PG4)
NetC64_1: C64.1 R23.2
NetC65_1: C65.1 R23.1 U3.25(COMP3)
NetC66_1: C66.1 U3.33(CB4)
NetC66_2: C66.2 L4.1 U3.32(SW4)
NetC70_1: C70.1 R26.1 R29.2 U3.35(VFB4)
NetC71_1: C71.1 TP21.1(PIN)
NetC71_2: C71.2 C73.2 R28.2 U3.40(RCLOCK_SYNC)
NetC72_1: C72.1 R27.2
NetC74_1: C74.1 R27.1 U3.36(COMP4)
NetD1_1: D1.1(K) Q1.3(D)
NetD1_2: D1.2(A) R30.1
NetQ1_1: Q1.1(G) R31.1 U3.17(PGOOD)
NetR14_1: R14.1 U3.39(~{RST})
NetR25_2: R25.2 U3.38(I2CADDR)

Not connected (* = marked no-connect by the designer): J28 3*; U3 13(ENSW2)* 27(ENSW3)* 34(ENSW4)* 41(I2CALERT)* 44(CLK_OUT)* 48(ENSW1/ENSEQ)*

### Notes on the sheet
- Switching Power Supply
- Power Jack
- (near J28) +6 to +16 VDC
- (near U3) I2C Addr: 1101001
- Power LED
- Title
- Size:
- Date:
- C
- Sheet
- of

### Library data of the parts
C30 = 001346: Ceramic capacitor; Manufacturer: Taiyo Yuden; partnumber: 001346; Description 2: SM-0603, 20%, 10V, X5R; ValueFloat: 1E-5; Tolerance (%): 20; x_lifecycle_status: Production
C31 = 000824: Ceramic capacitor; Manufacturer: Taiyo Yuden; partnumber: 000824; Description 2: 0402, 6.3V; ValueFloat: 4.7E-6; Tolerance (%): 20
C32 = 001926: Partnumber: 001926; manufacturer: TDK; ValueFloat: 3.3E-6; x_tolerance: 20
C33 C46 C57 = 001172: Ceramic Capacitor; Manufacturer: TDK; partnumber: 001172; Description 2: SM-1206, 35V, 20%; ValueFloat: 2.2E-5; Tolerance (%): 20; x_voltage-rating: 35
C34 C47 C58 = 001073: Ceramic capacitor; Manufacturer: Taiyo Yuden; partnumber: 001073; Description 2: 0402, 25V; ValueFloat: 1E-7; Tolerance (%): 10
C35 C38 C43 C45 C48 C51 C55 C56 C59 C63 C66 C67 = 000070: Ceramic capacitor; Manufacturer: Kemet; partnumber: 000070; Description 2: SM-0402, 10%, 10v; ValueFloat: 1E-7; Tolerance (%): 10
C36 = 001532: Polarized; Partnumber: 001532; manufacturer: Panasonic; ValueFloat: 0.00022; id: 155442; inventory_price: 0.2; x_tolerance: 20; x_voltage-rating: 25
C37 = 001073: Ceramic capacitor; Manufacturer: Taiyo Yuden; partnumber: 001073; Description 2: 0402, 25V; ValueFloat: 1E-7; Tolerance (%): 10; Voltage: 25V
C39 C40 C49 C50 C60 C61 C68 C69 = 001284: Ceramic capacitor; Manufacturer: Taiyo Yuden; partnumber: 001284; Description 2: SM-1206, 10%, 10v, X7R; ValueFloat: 2.2E-5; Tolerance (%): 10; x_lifecycle_status: Production
C41 C52 = 001004: Partnumber: 001004; manufacturer: Kemet; manufacturer_pn: C0402C560J5GACTU; ValueFloat: 5.6E-11; id: 25707; inventory_price: 0.0024; x_temperature_characteristic: C0G; x_tolerance: 5
C42 C53 C64 C72 = 000930: Ceramic capacitor; Manufacturer: Kemet; partnumber: 000930; Description 2: 0402, 50V; ValueFloat: 4.7E-9; Tolerance (%): 10
C44 C54 C65 C74 = 000807: Ceramic capacitor; Manufacturer: Kemet; partnumber: 000807; Description 2: SM-0402, 5%, 50v, C0G; ValueFloat: 2.2E-11; Tolerance (%): 5
C62 C70 = 001004: Ceramic capacitor; Manufacturer: Kemet; partnumber: 001004; Description 2: SM-0402, 5%, 50v; ValueFloat: 5.6E-11; Tolerance (%): 5
C71 = 000400: Partnumber: 000400; manufacturer: Kemet; manufacturer_pn: C0402C101J5GACTU; ValueFloat: 1E-10; id: 3829; inventory_price: 0.003; reorder_quantity: 200
C73 = 000962: Ceramic capacitor; Manufacturer: Murata; partnumber: 000962; Description 2: SM-0402, 50V; ValueFloat: 5E-12; Tolerance (%): 3.125
D1 = 001433: LED; Manufacturer: Dialight; Manufacturer_PN: 598-8070-107F; partnumber: 001433; Description 2: SM-0603, green; x_lifecycle_status: Production
J28 = DCPOWER: DC power connector - high current; manufacturer: CUI Inc.; partnumber: 000356
L1-L4 = 001543: Power inductor, 2.2uH, 7A, 12.7mOhm; Manufacturer: Coilcraft; partnumber: 001543; ValueFloat: 2.2E-6; Tolerance (%): 20; x_lifecycle_status: Production
Q1 = 001237: N-Channel MOSFET; PartNumber: 001237; manufacturer: Fairchild Semiconductor; manufacturer_pn: FDN337N; PackageDocument: 1995/1996; id: 48493; inventory_price: 0.2466
R14 R15 R31 = 001521: Thick-film resistor; Manufacturer: Vishay; partnumber: 001521; Description 2: SM-0402, 1%, 1/16W; ValueFloat: 10000; Tolerance (%): 1; x_lifecycle_status: Production
R16 R19 R22 = 001091: Partnumber: 001091; manufacturer: Vishay; manufacturer_pn: CRCW040231K6FKED; ValueFloat: 31600; id: 32220; inventory_price: 0.0015; x_tolerance: 1
R17 R20 R24 R29 = 001521: as R3 on sheet MC1
R18 R21 R23 R27 = 001121: Thick-film resistor; Manufacturer: Vishay; partnumber: 001121; Description 2: SM-0402, 1%, 1/16W; ValueFloat: 15000; Tolerance (%): 1
R25 = 001122: Partnumber: 001122; manufacturer: Vishay; ValueFloat: 39200; description: Thick-film resistor; x_tolerance: 1
R26 = 001157: Partnumber: 001157; manufacturer: Vishay; manufacturer_pn: CRCW040252K3FKED; ValueFloat: 52300; id: 36019; inventory_price: 0.0019; x_tolerance: 1
R28 = 001618: Thick-film resistor; Manufacturer: Vishay; partnumber: 001618; Description 2: SM-0402, 1%, 1/16W; ValueFloat: 374000; Tolerance (%): 1; x_lifecycle_status: Production
R30 = 001162: Thick-film resistor; Manufacturer: Vishay; partnumber: 001162; Description 2: SM-0402, 1%, 1/16W; ValueFloat: 2000; Tolerance (%): 1
TP17-TP21 = TESTPOINT-SMD40: Test point, surface-mount, 40mil
U3 = 001511: 4-channel switching regulator with PMBus; Manufacturer: Texas Instruments; partnumber: 001511; Description 2: Vin: 4.5V to 18V, Vout: 0.6V to 90% Vin,PMBus, VQFN-48; x_lifecycle_status: Production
